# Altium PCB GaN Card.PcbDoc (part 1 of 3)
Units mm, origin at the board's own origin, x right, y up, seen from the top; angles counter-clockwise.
Board outline 50 x 40 mm, 6 copper layers (Top Layer, MidLayer1, MidLayer2, MidLayer3, MidLayer4, Bottom Layer), stack 1.981 mm thick; 88 components, 77 nets, 322 pads, 257 vias.
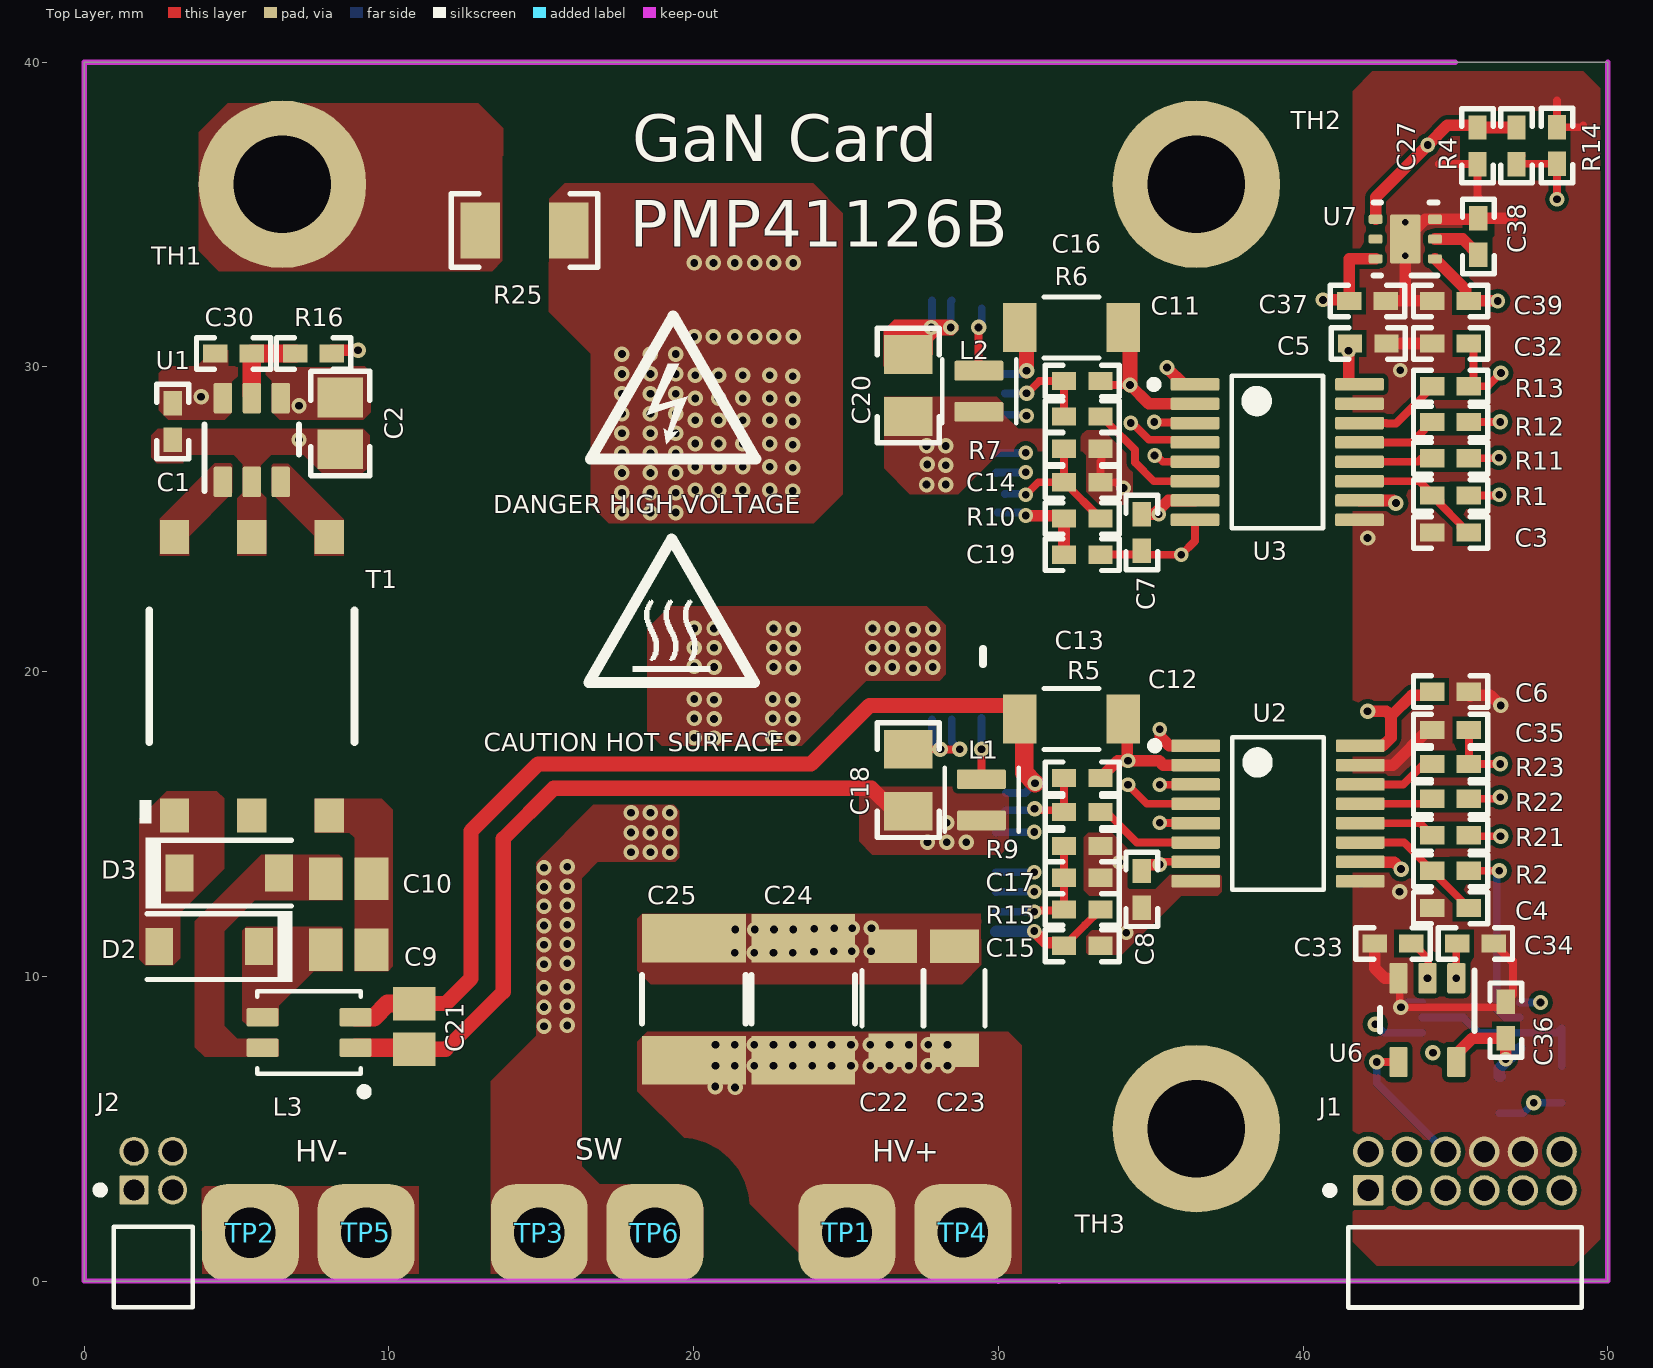
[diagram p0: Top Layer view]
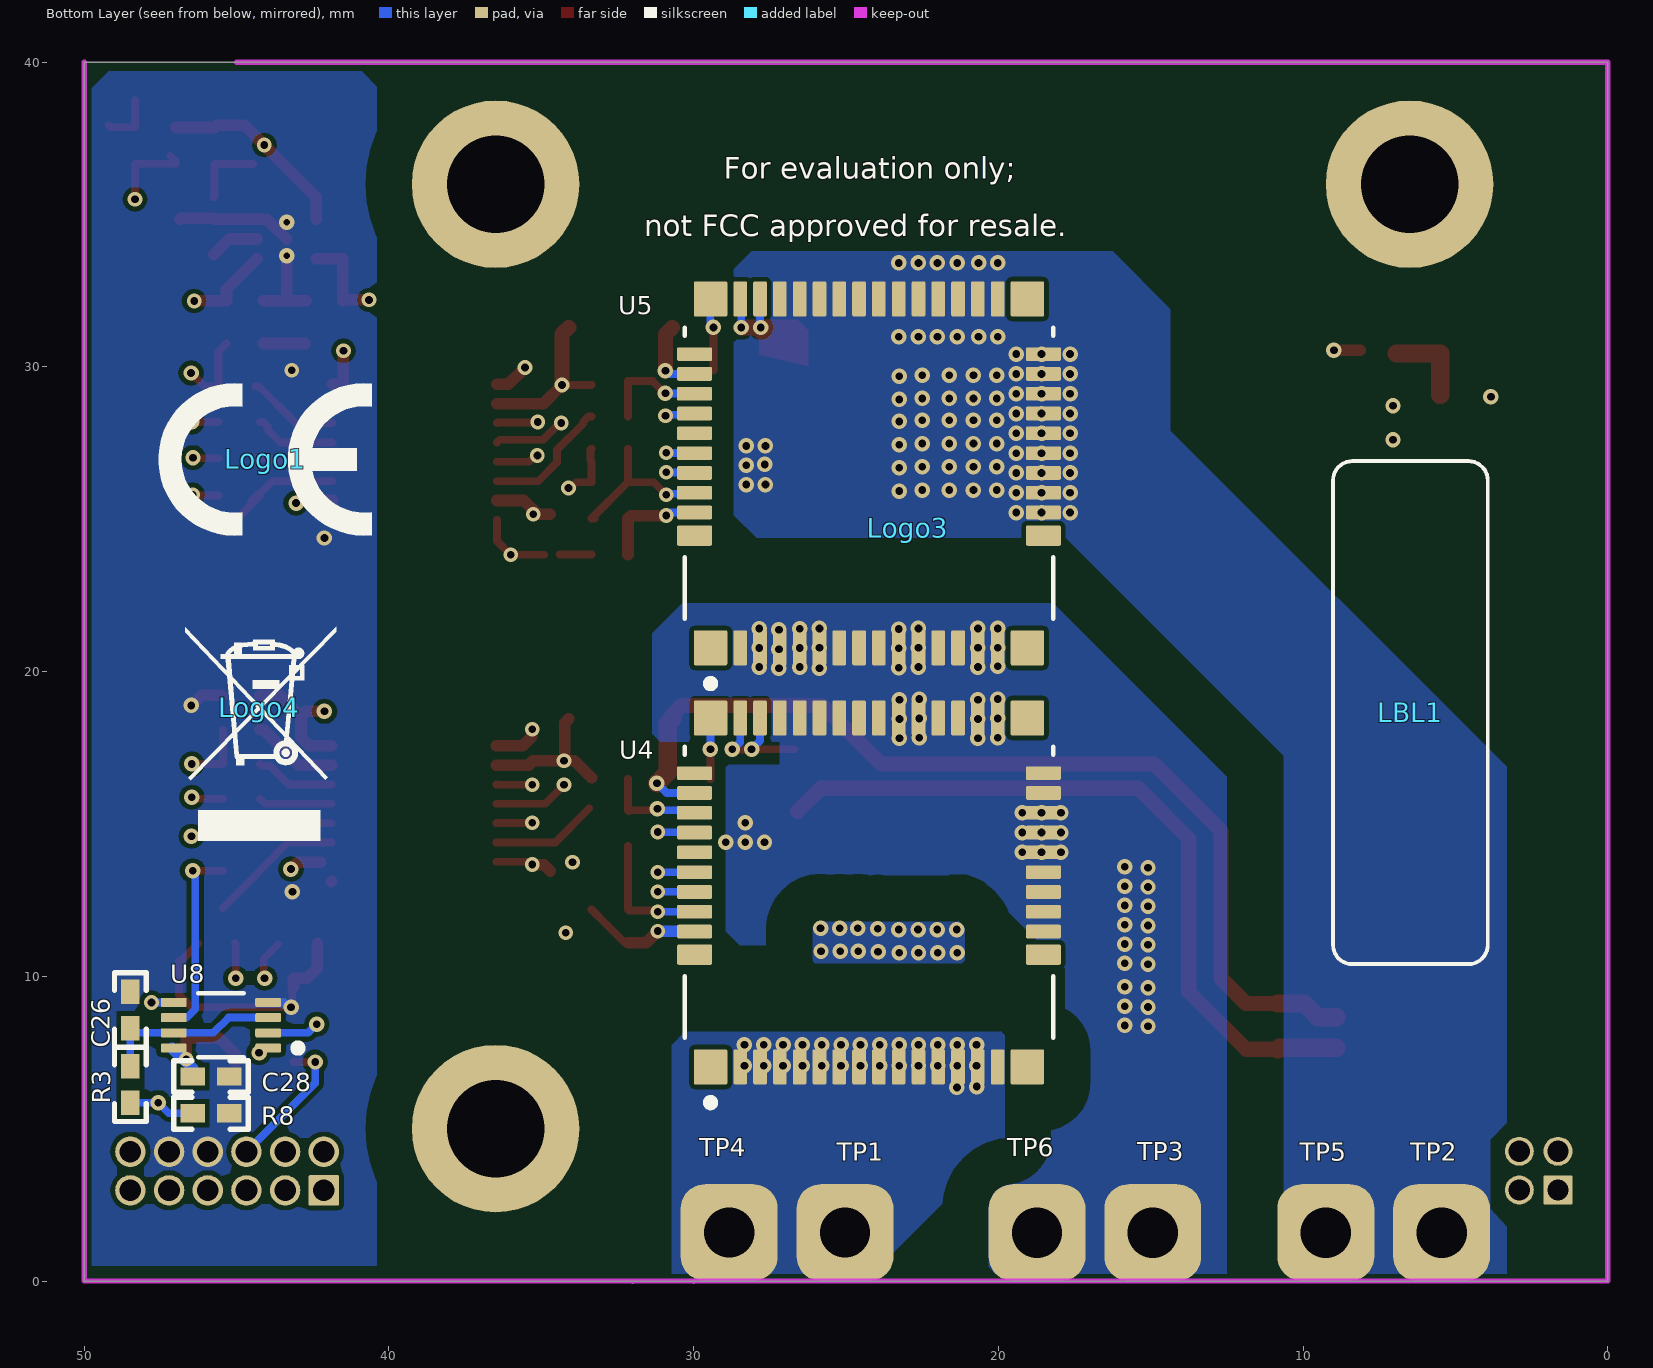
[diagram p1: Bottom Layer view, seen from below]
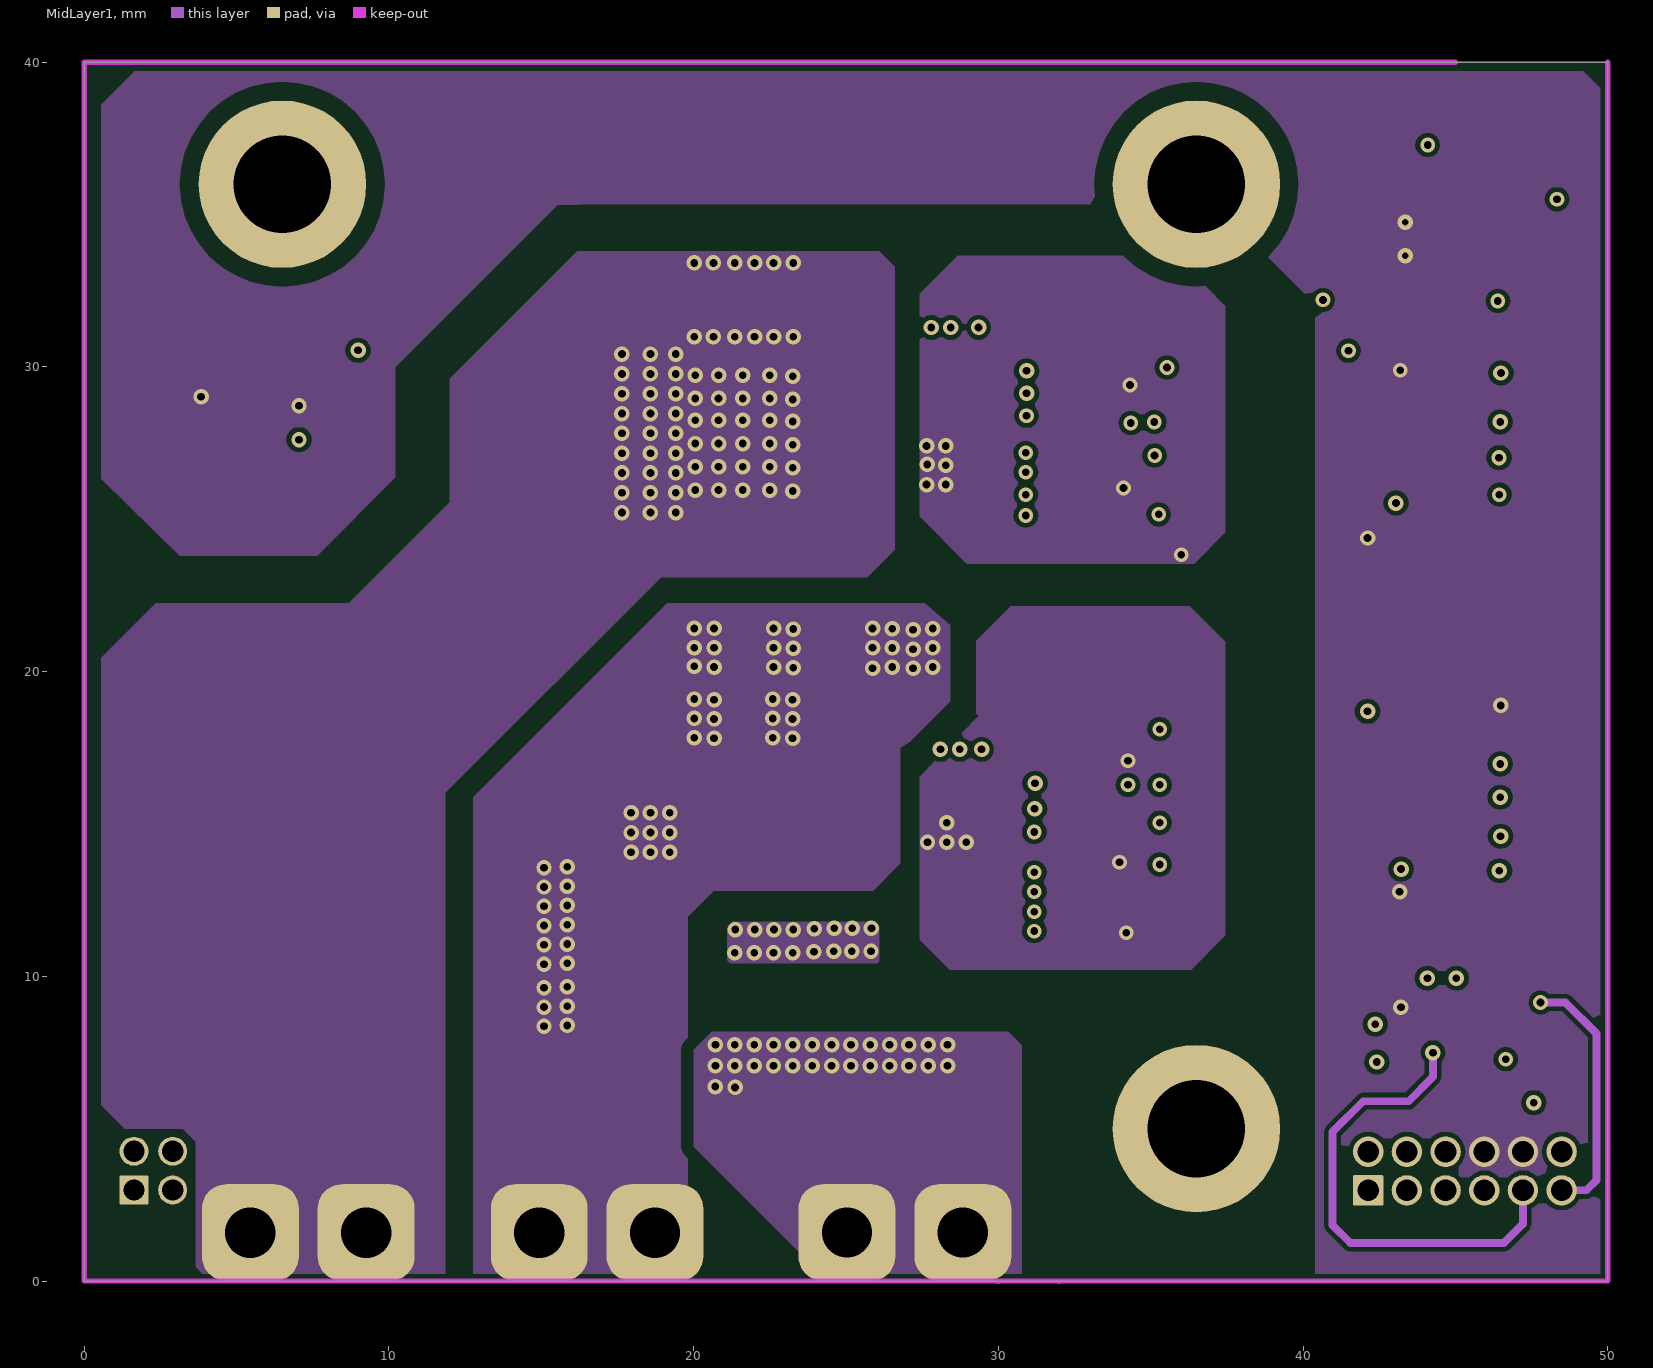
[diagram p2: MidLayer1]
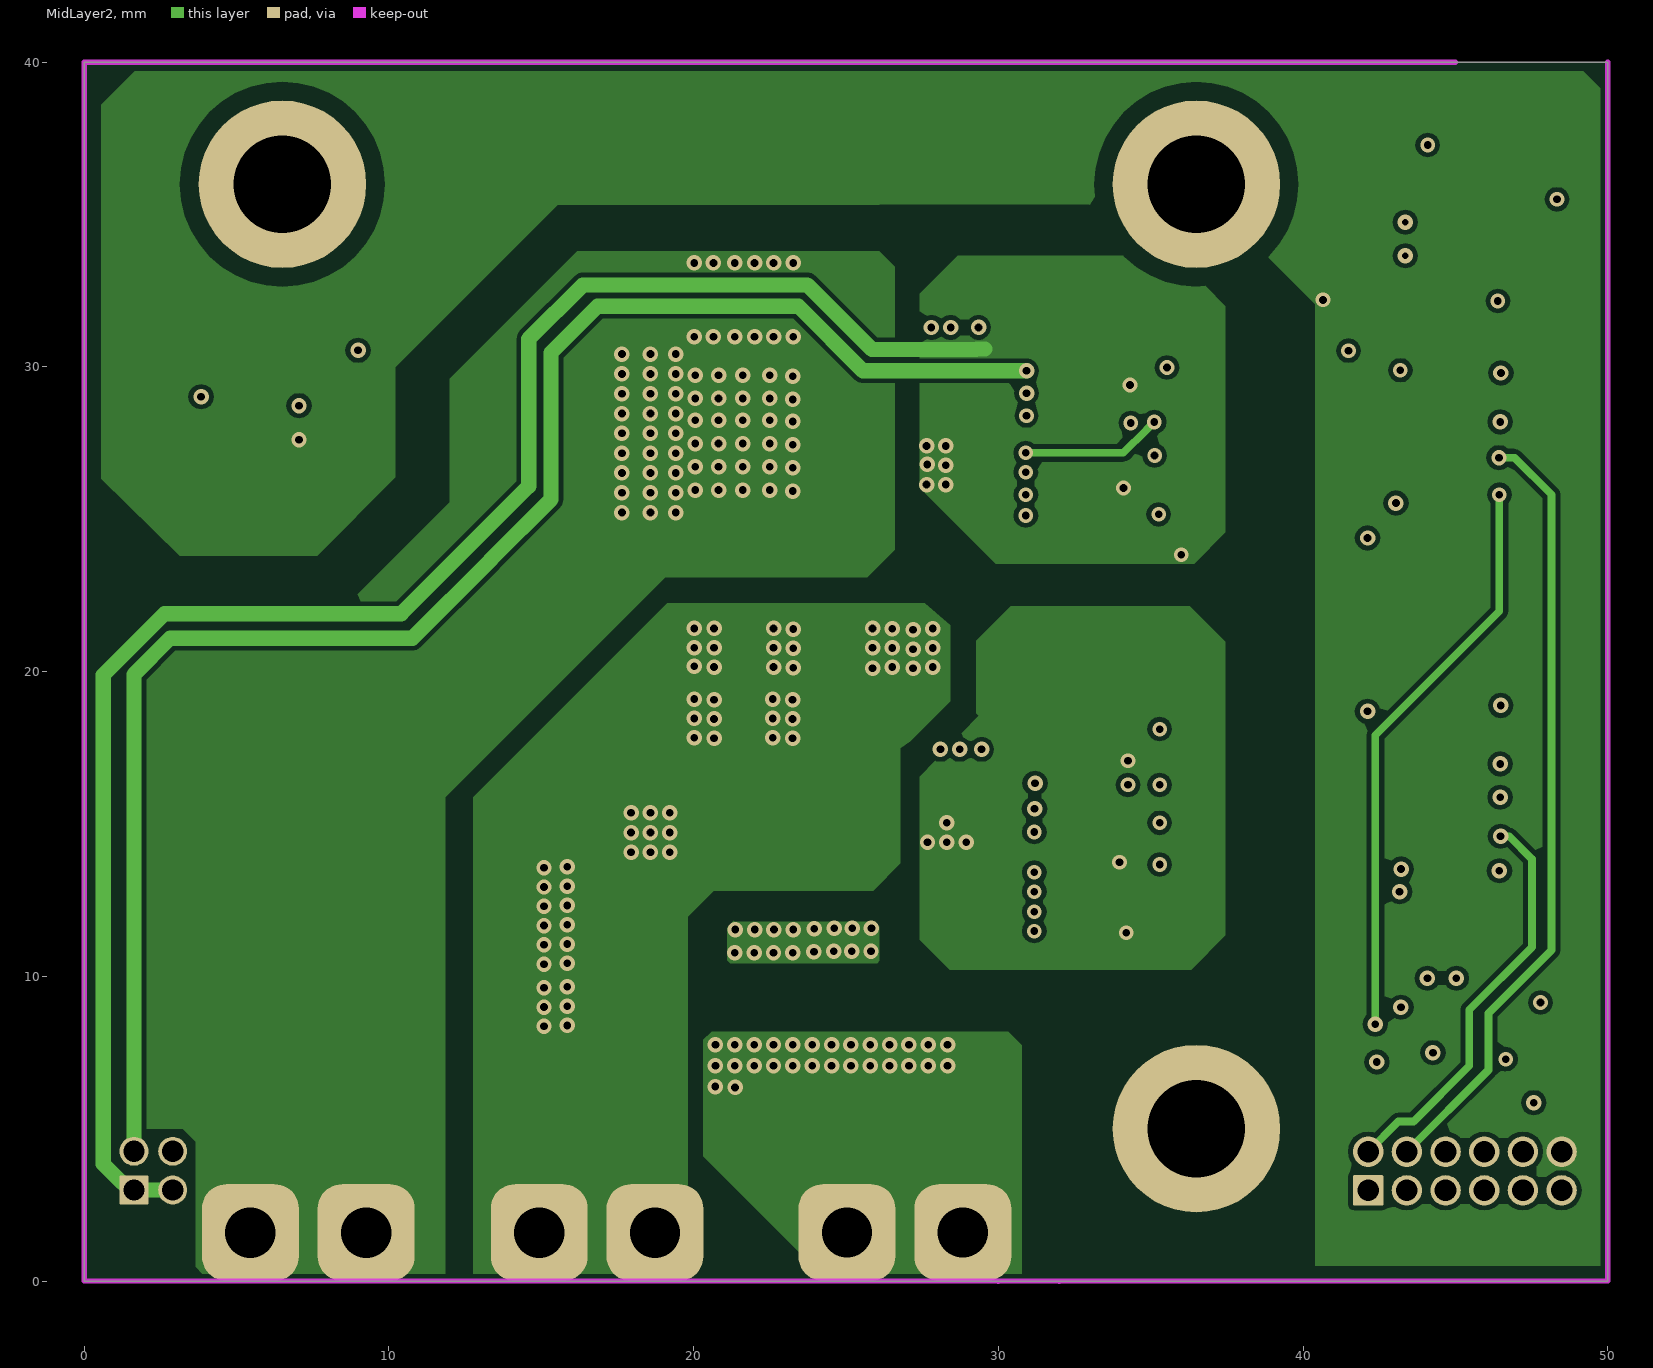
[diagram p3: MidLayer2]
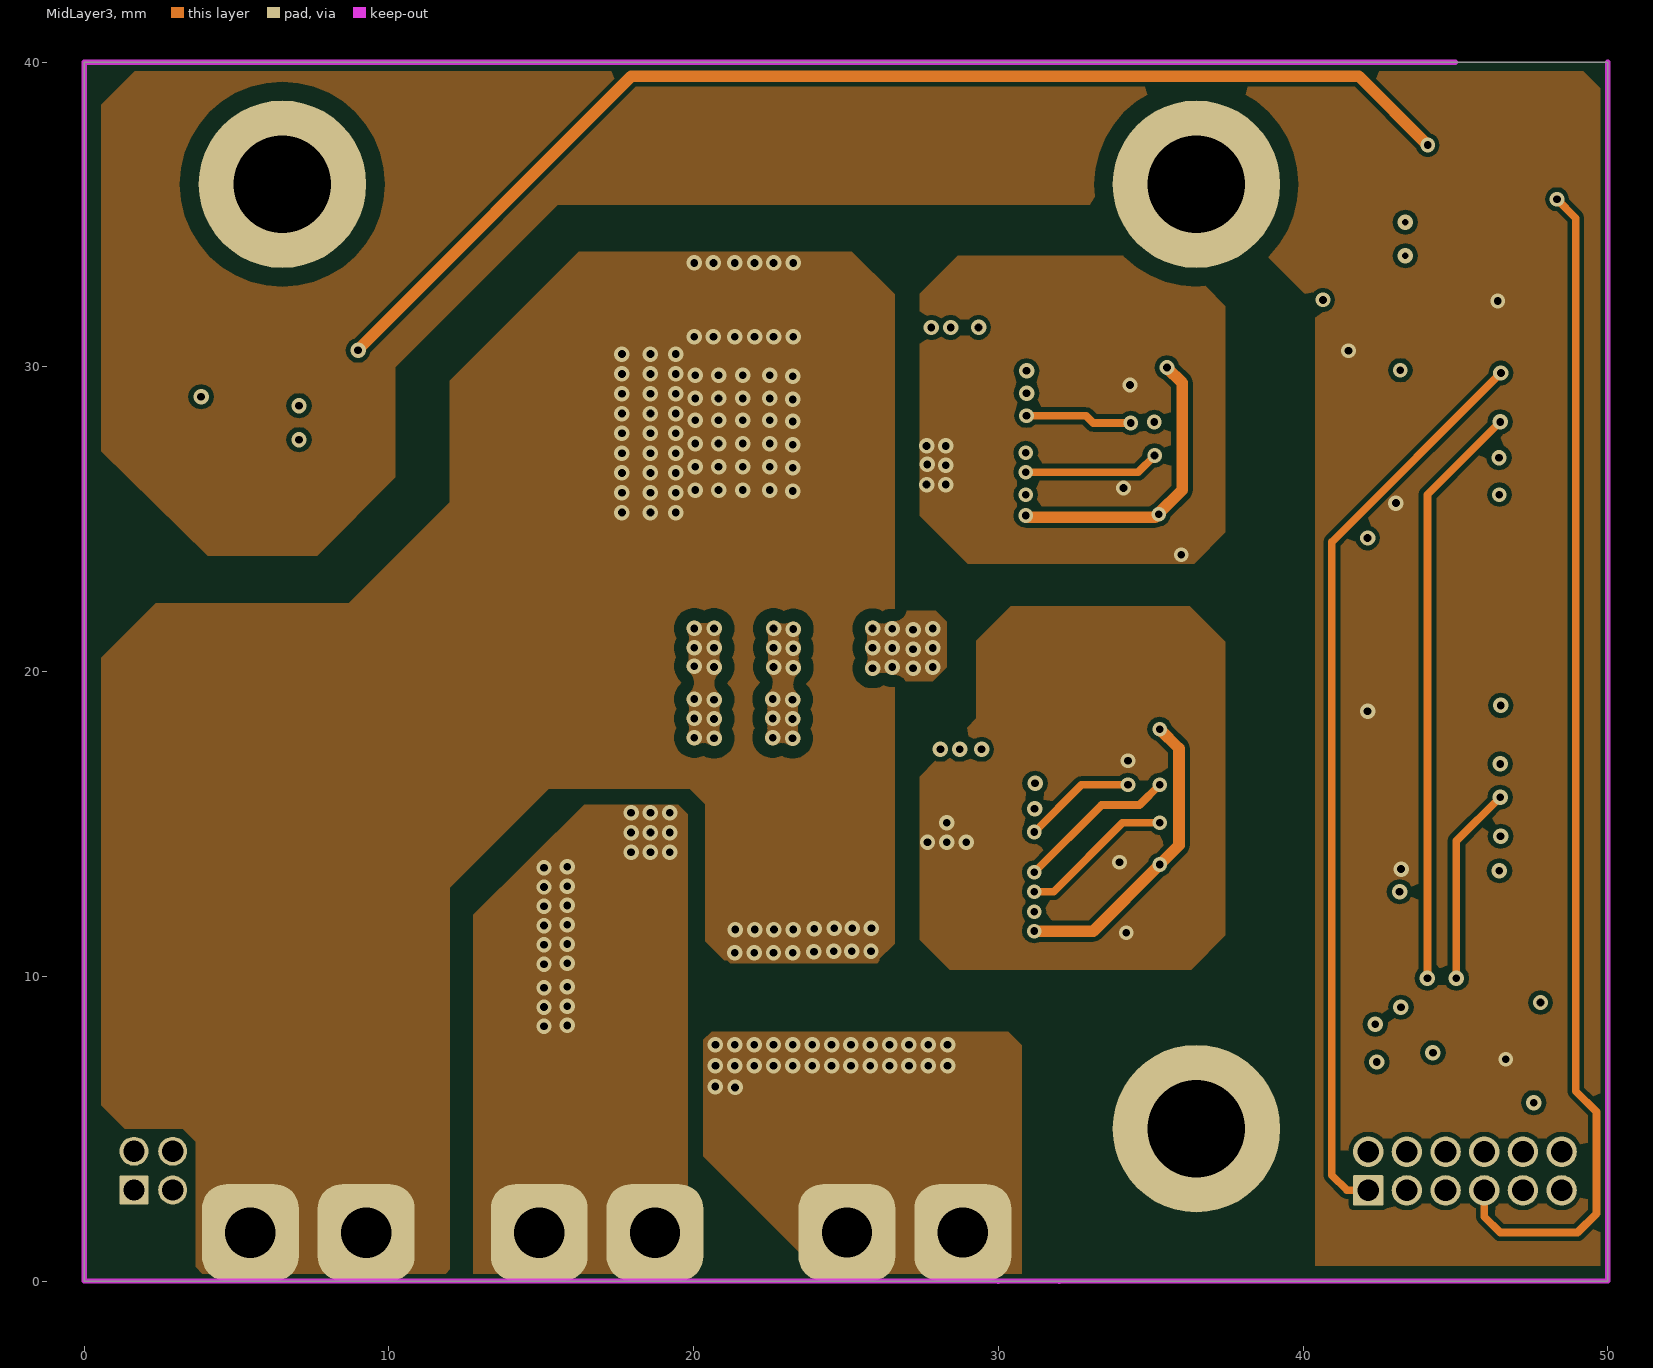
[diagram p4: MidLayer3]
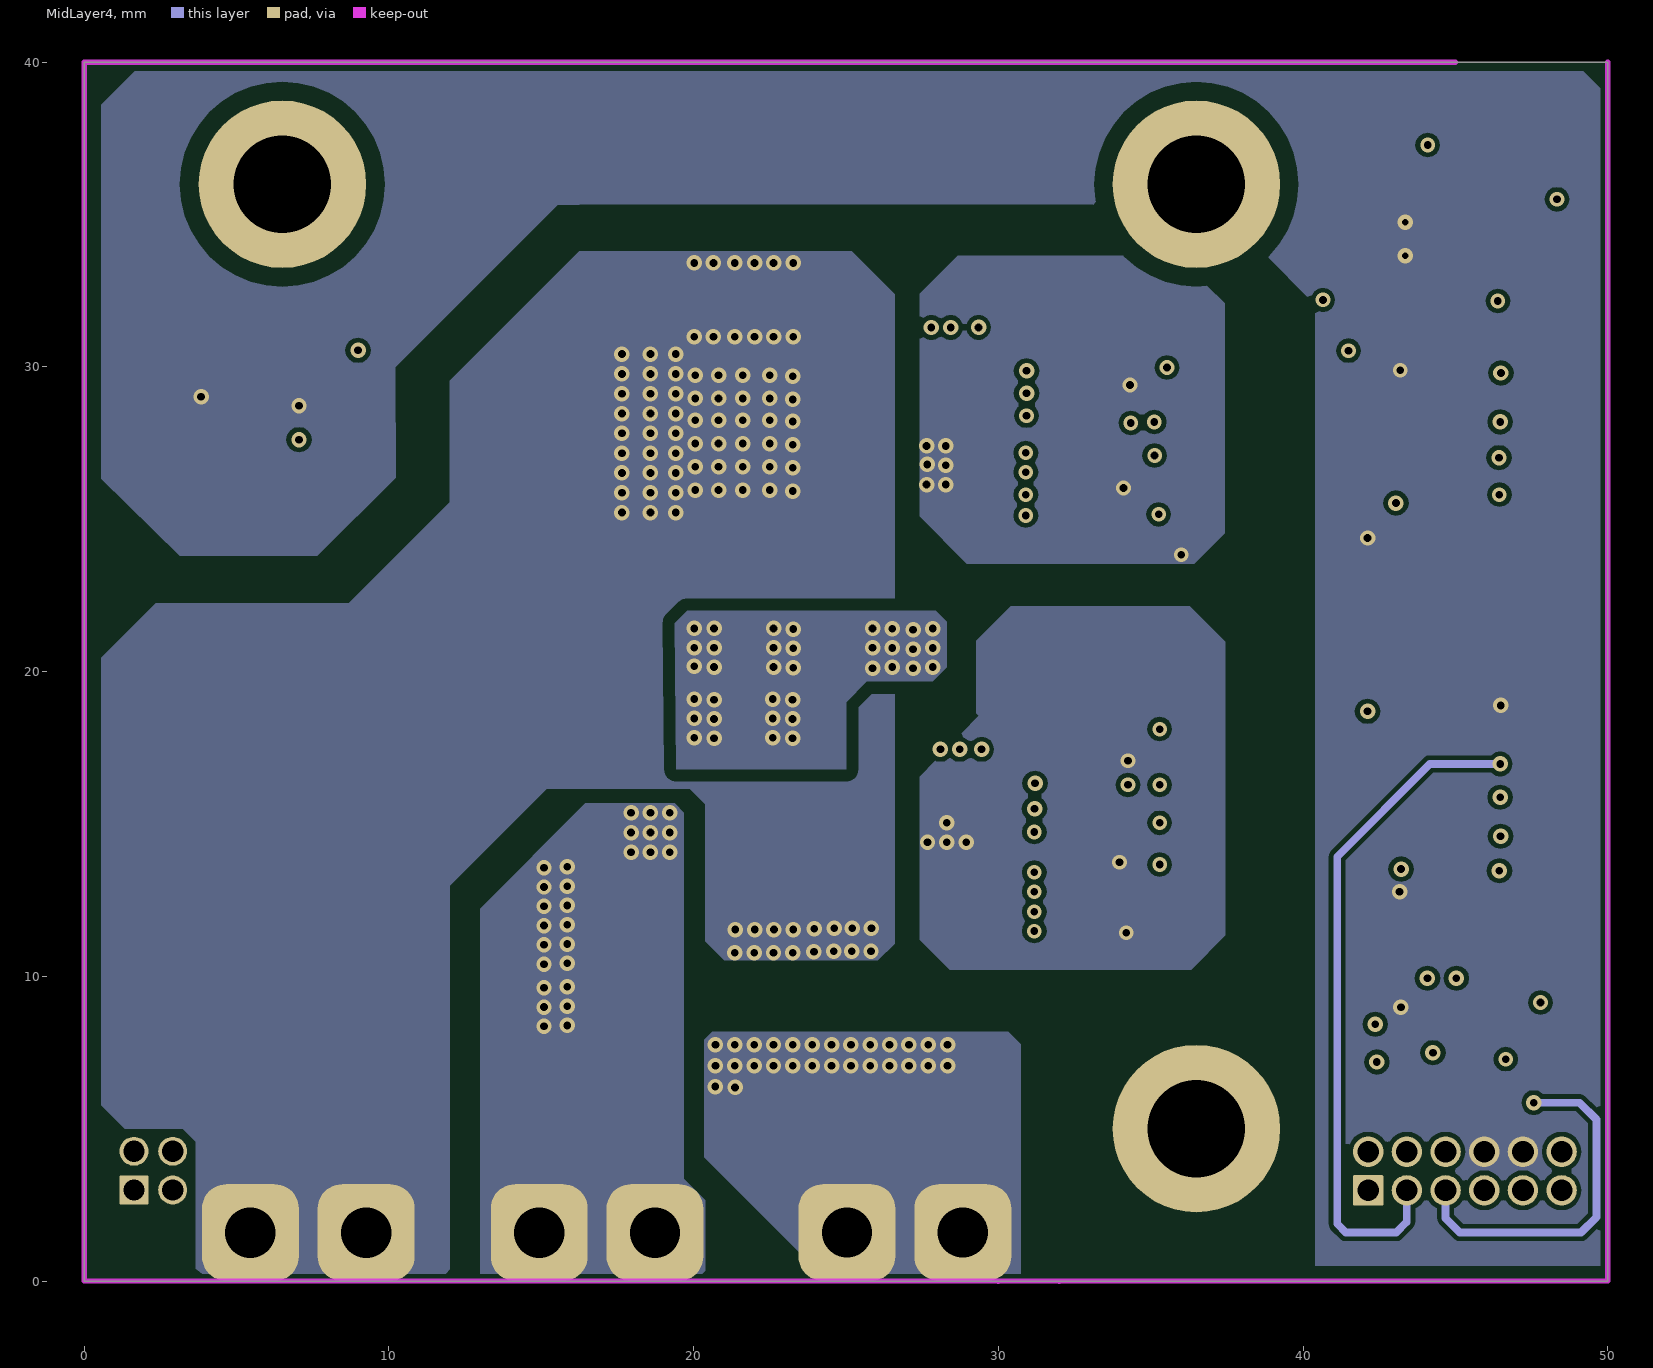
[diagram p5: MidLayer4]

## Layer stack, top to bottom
Top Solder: solder mask 0.0102, Solder Resist, Dk 3.5
Top Layer: signal copper 0.0711
Dielectric 1: prepreg 0.1168, FR-4 High Tg, Dk 4.2
MidLayer1: signal copper 0.0711
Dielectric 2: core 0.602, FR-4 High Tg, Dk 4.2
MidLayer2: signal copper 0.0711
4.6: prepreg 0.1168, FR-4 High Tg, Dk 4.2
MidLayer3: signal copper 0.0711
Dielectric 4: core 0.602, Dk 4.2
MidLayer4: signal copper 0.0711
Dielectric 5: prepreg 0.1168, Dk 4.2
Bottom Layer: signal copper 0.0711
Bottom Solder: solder mask 0.0102, Solder Resist, Dk 3.5

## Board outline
0,0 0,40 50,40 50,0 10,0

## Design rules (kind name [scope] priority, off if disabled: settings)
AcuteAngle [All] p1: minimum=4.50000000000000E+0001 checktracksonly=FALSE
AssemblyTestPointUsage [All] p1: valid=2
BoardOutlineClearance "Paste Layer 2" [OnLayer('Bottom Solder')] p1: gap=0 ignorepadtopadclearanceinfootprint=FALSE
BoardOutlineClearance "Paste Layer 1" [OnLayer('Top Solder')] p2: gap=0 ignorepadtopadclearanceinfootprint=FALSE
BoardOutlineClearance [OnCopper] p3: gap=0 ignorepadtopadclearanceinfootprint=FALSE
Clearance Clearance_VSW_Mid1 [(OnMultiLayer Or OnMid) And InNetClass('VSWNET') vs OnMid And Not InNetClass('VSWNET')] p1: gap=0.406 ignorepadtopadclearanceinfootprint=TRUE
Clearance Clearance_Screw_Top [InNetClass('Screw') vs OnLayer('Top Layer') And Not InNetClass('Screw')] p2: gap=1.524 ignorepadtopadclearanceinfootprint=TRUE
Clearance Clearance_Screw_Bottom [InNetClass('Screw') vs OnLayer('Bottom Layer') And Not InNetClass('Screw')] p3: gap=1.524 ignorepadtopadclearanceinfootprint=TRUE
Clearance Clearance_Screw_Other [InNetClass('Screw') vs Not OnLayer('Top Layer') AND Not OnLayer('Bottom Layer') AND Not InNetClass('Screw')] p4: gap=0.6 ignorepadtopadclearanceinfootprint=TRUE
Clearance Clearance_VSW_Mid2 [(OnMultiLayer Or OnMid) And Not InNetClass('VSWNET') vs OnMid And InNetClass('VSWNET')] p5: gap=0.406 ignorepadtopadclearanceinfootprint=TRUE
Clearance Clearance_VSW [InNetClass('VSWNET')   and OnCopper vs Not InNetClass('VSWNET') and OnCopper] p6: gap=1.524 ignorepadtopadclearanceinfootprint=TRUE
Clearance Clearance_VHV_Mid1 [(OnMultiLayer Or OnMid) And InNetClass('VHV') vs OnMid And Not InNetClass('VHV')] p7: gap=0.406 ignorepadtopadclearanceinfootprint=TRUE
Clearance Clearance_VHV_Mid2 [(OnMultiLayer Or OnMid) And Not InNetClass('VHV') vs OnMid And InNetClass('VHV')] p8: gap=0.406 ignorepadtopadclearanceinfootprint=TRUE
Clearance Clearance_VHV [InNetClass('VHV') vs Not InNetClass('VHV') and OnCopper] p9: gap=1.524 ignorepadtopadclearanceinfootprint=FALSE
Clearance Clearance_INGND [InNetClass('INGND') and OnCopper vs Not InNetClass('INGND')  and OnCopper] p10: gap=1.524 ignorepadtopadclearanceinfootprint=FALSE
Clearance [All] p11: gap=0.152 ignorepadtopadclearanceinfootprint=FALSE
ComponentClearance ComponentClearance_Shunt [InComponentClass('Header') vs InComponentClass('Shunt')] p1: gap=0 collisioncheckmode=3 verticalgap=0 showdistances=FALSE
ComponentClearance ComponentClearance_MountingHoles_FiducialMarks [InComponentClass('Mounting Holes') vs InComponentClass('FiducialMark')] p2 off: gap=1.27 collisioncheckmode=3 verticalgap=0.254 showdistances=FALSE
ComponentClearance ComponentClearance_Logo [InComponentClass('Logo')] p3: gap=0 collisioncheckmode=3 verticalgap=0.254 showdistances=FALSE
ComponentClearance ComponentClearance_ScrewToNut [(HasFootprint('NY PMS 440 0025 PH')) vs (HasFootprint('Keystone_1902C'))] p4: gap=0.127 collisioncheckmode=3 verticalgap=0.254 showdistances=FALSE
ComponentClearance ComponentClearance_MountingHoles [InComponentClass('Mounting Holes')] p5: gap=6.35 collisioncheckmode=3 verticalgap=2540 showdistances=FALSE
ComponentClearance ComponentClearance_SmallPassives [HasFootprint('0201*') or HasFootprint('0402*') or HasFootprint('0508') or HasFootprint('0603*') or HasFootprint('0612') or HasFootprint('0805*') or HasFootprint('0815*') or HasFootprint('0830*') or HasFootprint('1206*') or HasFootprint('1210*') or HasFootprint('1808*') or HasFootprint('1812*') or HasFootprint('1825*') or HasFootprint('2010*') or HasFootprint('2220*') or HasFootprint('2225*') or HasFootprint('2512*') or HasFootprint('2728*') or HasFootprint('3518*') vs HasFootprint('0201*') or HasFootprint('0402*') or HasFootprint('0508') or HasFootprint('0603*') or HasFootprint('0612') or HasFootprint('0805*') or HasFootprint('0815*') or HasFootprint('0830*') or HasFootprint('1206*') or HasFootprint('1210*') or HasFootprint('1808*') or HasFootprint('1812*') or HasFootprint('1825*') or HasFootprint('2010*') or HasFootprint('2220*') or HasFootprint('2225*') or HasFootprint('2512*') or HasFootprint('2728*') or HasFootprint('3518*')] p6: gap=0.025 collisioncheckmode=3 verticalgap=0.254 showdistances=FALSE
ComponentClearance ComponentClearance_THtoSMT [IsThruComponent vs IsSMTComponent] p7: gap=0.254 collisioncheckmode=3 verticalgap=0.762 showdistances=FALSE
ComponentClearance ComponentClearance_THtoTH [IsThruComponent vs IsThruComponent] p8: gap=0.3 collisioncheckmode=3 verticalgap=0.762 showdistances=FALSE
ComponentClearance [All] p9: gap=0.025 collisioncheckmode=3 verticalgap=0.254 showdistances=FALSE
DiffPairsRouting [All] p1: maxlimit=2.54 minlimit=0.254 mostfreqgap=0.254 substack1={A02F224D-4808-492E-A71F-5F5656FBF0D4} toplayer_{a02f224d-4808-492e-a71f-5f5656fbf0d4}_minwidth=0.381 toplayer_{a02f224d-4808-492e-a71f-5f5656fbf0d4}_maxwidth=0.381 toplayer_{a02f224d-4808-492e-a71f-5f5656fbf0d4}_prefwidth=0.381 midlayer1_{a02f224d-4808-492e-a71f-5f5656fbf0d4}_minwidth=0.381 midlayer1_{a02f224d-4808-492e-a71f-5f5656fbf0d4}_maxwidth=0.381 midlayer1_{a02f224d-4808-492e-a71f-5f5656fbf0d4}_prefwidth=0.381 midlayer2_{a02f224d-4808-492e-a71f-5f5656fbf0d4}_minwidth=0.381 midlayer2_{a02f224d-4808-492e-a71f-5f5656fbf0d4}_maxwidth=0.381 midlayer2_{a02f224d-4808-492e-a71f-5f5656fbf0d4}_prefwidth=0.381 midlayer3_{a02f224d-4808-492e-a71f-5f5656fbf0d4}_minwidth=0.381 midlayer3_{a02f224d-4808-492e-a71f-5f5656fbf0d4}_maxwidth=0.381 midlayer3_{a02f224d-4808-492e-a71f-5f5656fbf0d4}_prefwidth=0.381 midlayer4_{a02f224d-4808-492e-a71f-5f5656fbf0d4}_minwidth=0.381 midlayer4_{a02f224d-4808-492e-a71f-5f5656fbf0d4}_maxwidth=0.381 midlayer4_{a02f224d-4808-492e-a71f-5f5656fbf0d4}_prefwidth=0.381 bottomlayer_{a02f224d-4808-492e-a71f-5f5656fbf0d4}_minwidth=0.381 bottomlayer_{a02f224d-4808-492e-a71f-5f5656fbf0d4}_maxwidth=0.381 bottomlayer_{a02f224d-4808-492e-a71f-5f5656fbf0d4}_prefwidth=0.381 substack2={B838D286-A00B-4EE2-88E1-F79279CC64B4} toplayer_{b838d286-a00b-4ee2-88e1-f79279cc64b4}_minwidth=0.381 toplayer_{b838d286-a00b-4ee2-88e1-f79279cc64b4}_maxwidth=0.381 toplayer_{b838d286-a00b-4ee2-88e1-f79279cc64b4}_prefwidth=0.381 midlayer1_{b838d286-a00b-4ee2-88e1-f79279cc64b4}_minwidth=0.381 midlayer1_{b838d286-a00b-4ee2-88e1-f79279cc64b4}_maxwidth=0.381 midlayer1_{b838d286-a00b-4ee2-88e1-f79279cc64b4}_prefwidth=0.381 midlayer2_{b838d286-a00b-4ee2-88e1-f79279cc64b4}_minwidth=0.381 midlayer2_{b838d286-a00b-4ee2-88e1-f79279cc64b4}_maxwidth=0.381 midlayer2_{b838d286-a00b-4ee2-88e1-f79279cc64b4}_prefwidth=0.381 midlayer3_{b838d286-a00b-4ee2-88e1-f79279cc64b4}_minwidth=0.381 midlayer3_{b838d286-a00b-4ee2-88e1-f79279cc64b4}_maxwidth=0.381 midlayer3_{b838d286-a00b-4ee2-88e1-f79279cc64b4}_prefwidth=0.381 midlayer4_{b838d286-a00b-4ee2-88e1-f79279cc64b4}_minwidth=0.381 midlayer4_{b838d286-a00b-4ee2-88e1-f79279cc64b4}_maxwidth=0.381 midlayer4_{b838d286-a00b-4ee2-88e1-f79279cc64b4}_prefwidth=0.381 bottomlayer_{b838d286-a00b-4ee2-88e1-f79279cc64b4}_minwidth=0.381 bottomlayer_{b838d286-a00b-4ee2-88e1-f79279cc64b4}_maxwidth=0.381 bottomlayer_{b838d286-a00b-4ee2-88e1-f79279cc64b4}_prefwidth=0.381 substack3={88BCB183-C685-456E-B90A-365A53404C2C} toplayer_{88bcb183-c685-456e-b90a-365a53404c2c}_minwidth=0.381 toplayer_{88bcb183-c685-456e-b90a-365a53404c2c}_maxwidth=0.381 toplayer_{88bcb183-c685-456e-b90a-365a53404c2c}_prefwidth=0.381 midlayer1_{88bcb183-c685-456e-b90a-365a53404c2c}_minwidth=0.381 midlayer1_{88bcb183-c685-456e-b90a-365a53404c2c}_maxwidth=0.381 midlayer1_{88bcb183-c685-456e-b90a-365a53404c2c}_prefwidth=0.381 midlayer2_{88bcb183-c685-456e-b90a-365a53404c2c}_minwidth=0.381 midlayer2_{88bcb183-c685-456e-b90a-365a53404c2c}_maxwidth=0.381 midlayer2_{88bcb183-c685-456e-b90a-365a53404c2c}_prefwidth=0.381 midlayer3_{88bcb183-c685-456e-b90a-365a53404c2c}_minwidth=0.381 midlayer3_{88bcb183-c685-456e-b90a-365a53404c2c}_maxwidth=0.381 midlayer3_{88bcb183-c685-456e-b90a-365a53404c2c}_prefwidth=0.381 midlayer4_{88bcb183-c685-456e-b90a-365a53404c2c}_minwidth=0.381 midlayer4_{88bcb183-c685-456e-b90a-365a53404c2c}_maxwidth=0.381 midlayer4_{88bcb183-c685-456e-b90a-365a53404c2c}_prefwidth=0.381 bottomlayer_{88bcb183-c685-456e-b90a-365a53404c2c}_minwidth=0.381 bottomlayer_{88bcb183-c685-456e-b90a-365a53404c2c}_maxwidth=0.381 bottomlayer_{88bcb183-c685-456e-b90a-365a53404c2c}_prefwidth=0.381 substack4={4C8C2325-90D5-40B8-8B6B-4F66D44EFE25} toplayer_{4c8c2325-90d5-40b8-8b6b-4f66d44efe25}_minwidth=0.381 toplayer_{4c8c2325-90d5-40b8-8b6b-4f66d44efe25}_maxwidth=0.381 toplayer_{4c8c2325-90d5-40b8-8b6b-4f66d44efe25}_prefwidth=0.381 midlayer1_{4c8c2325-90d5-40b8-8b6b-4f66d44efe25}_minwidth=0.381 midlayer1_{4c8c2325-90d5-40b8-8b6b-4f66d44efe25}_maxwidth=0.381 midlayer1_{4c8c2325-90d5-40b8-8b6b-4f66d44efe25}_prefwidth=0.381 midlayer2_{4c8c2325-90d5-40b8-8b6b-4f66d44efe25}_minwidth=0.381 midlayer2_{4c8c2325-90d5-40b8-8b6b-4f66d44efe25}_maxwidth=0.381 midlayer2_{4c8c2325-90d5-40b8-8b6b-4f66d44efe25}_prefwidth=0.381 midlayer3_{4c8c2325-90d5-40b8-8b6b-4f66d44efe25}_minwidth=0.381 midlayer3_{4c8c2325-90d5-40b8-8b6b-4f66d44efe25}_maxwidth=0.381 midlayer3_{4c8c2325-90d5-40b8-8b6b-4f66d44efe25}_prefwidth=0.381 midlayer4_{4c8c2325-90d5-40b8-8b6b-4f66d44efe25}_minwidth=0.381 midlayer4_{4c8c2325-90d5-40b8-8b6b-4f66d44efe25}_maxwidth=0.381 midlayer4_{4c8c2325-90d5-40b8-8b6b-4f66d44efe25}_prefwidth=0.381 bottomlayer_{4c8c2325-90d5-40b8-8b6b-4f66d44efe25}_minwidth=0.381 bottomlayer_{4c8c2325-90d5-40b8-8b6b-4f66d44efe25}_maxwidth=0.381 bottomlayer_{4c8c2325-90d5-40b8-8b6b-4f66d44efe25}_prefwidth=0.381 toplayer_minwidth=0.381 toplayer_maxwidth=0.381 toplayer_prefwidth=0.381 midlayer1_minwidth=0.381 midlayer1_maxwidth=0.381 midlayer1_prefwidth=0.381 midlayer2_minwidth=0.381 midlayer2_maxwidth=0.381 midlayer2_prefwidth=0.381 midlayer3_minwidth=0.381 midlayer3_maxwidth=0.381 midlayer3_prefwidth=0.381 midlayer4_minwidth=0.381 midlayer4_maxwidth=0.381 midlayer4_prefwidth=0.381 bottomlayer_minwidth=0.381 bottomlayer_maxwidth=0.381 bottomlayer_prefwidth=0.381 substack5={553D66F5-99EF-40B1-BA7C-73E3B04B176F} toplayer_{553d66f5-99ef-40b1-ba7c-73e3b04b176f}_minwidth=0.381 toplayer_{553d66f5-99ef-40b1-ba7c-73e3b04b176f}_maxwidth=0.381 toplayer_{553d66f5-99ef-40b1-ba7c-73e3b04b176f}_prefwidth=0.381 midlayer1_{553d66f5-99ef-40b1-ba7c-73e3b04b176f}_minwidth=0.381 midlayer1_{553d66f5-99ef-40b1-ba7c-73e3b04b176f}_maxwidth=0.381 midlayer1_{553d66f5-99ef-40b1-ba7c-73e3b04b176f}_prefwidth=0.381 midlayer2_{553d66f5-99ef-40b1-ba7c-73e3b04b176f}_minwidth=0.381 midlayer2_{553d66f5-99ef-40b1-ba7c-73e3b04b176f}_maxwidth=0.381 midlayer2_{553d66f5-99ef-40b1-ba7c-73e3b04b176f}_prefwidth=0.381 midlayer3_{553d66f5-99ef-40b1-ba7c-73e3b04b176f}_minwidth=0.381 midlayer3_{553d66f5-99ef-40b1-ba7c-73e3b04b176f}_maxwidth=0.381 midlayer3_{553d66f5-99ef-40b1-ba7c-73e3b04b176f}_prefwidth=0.381 midlayer4_{553d66f5-99ef-40b1-ba7c-73e3b04b176f}_minwidth=0.381 midlayer4_{553d66f5-99ef-40b1-ba7c-73e3b04b176f}_maxwidth=0.381 midlayer4_{553d66f5-99ef-40b1-ba7c-73e3b04b176f}_prefwidth=0.381 bottomlayer_{553d66f5-99ef-40b1-ba7c-73e3b04b176f}_minwidth=0.381 bottomlayer_{553d66f5-99ef-40b1-ba7c-73e3b04b176f}_maxwidth=0.381 bottomlayer_{553d66f5-99ef-40b1-ba7c-73e3b04b176f}_prefwidth=0.381 substack6={FF0C9878-5A48-402E-B013-8E2EEFCEDCCB} toplayer_{ff0c9878-5a48-402e-b013-8e2eefcedccb}_minwidth=0.381 toplayer_{ff0c9878-5a48-402e-b013-8e2eefcedccb}_maxwidth=0.381 toplayer_{ff0c9878-5a48-402e-b013-8e2eefcedccb}_prefwidth=0.381 midlayer1_{ff0c9878-5a48-402e-b013-8e2eefcedccb}_minwidth=0.381 midlayer1_{ff0c9878-5a48-402e-b013-8e2eefcedccb}_maxwidth=0.381 midlayer1_{ff0c9878-5a48-402e-b013-8e2eefcedccb}_prefwidth=0.381 midlayer2_{ff0c9878-5a48-402e-b013-8e2eefcedccb}_minwidth=0.381 midlayer2_{ff0c9878-5a48-402e-b013-8e2eefcedccb}_maxwidth=0.381 midlayer2_{ff0c9878-5a48-402e-b013-8e2eefcedccb}_prefwidth=0.381 midlayer3_{ff0c9878-5a48-402e-b013-8e2eefcedccb}_minwidth=0.381 midlayer3_{ff0c9878-5a48-402e-b013-8e2eefcedccb}_maxwidth=0.381 midlayer3_{ff0c9878-5a48-402e-b013-8e2eefcedccb}_prefwidth=0.381 midlayer4_{ff0c9878-5a48-402e-b013-8e2eefcedccb}_minwidth=0.381 midlayer4_{ff0c9878-5a48-402e-b013-8e2eefcedccb}_maxwidth=0.381 midlayer4_{ff0c9878-5a48-402e-b013-8e2eefcedccb}_prefwidth=0.381 bottomlayer_{ff0c9878-5a48-402e-b013-8e2eefcedccb}_minwidth=0.381 bottomlayer_{ff0c9878-5a48-402e-b013-8e2eefcedccb}_maxwidth=0.381 bottomlayer_{ff0c9878-5a48-402e-b013-8e2eefcedccb}_prefwidth=0.381 substack7={5BB5B65B-6C7F-4868-A6AE-66DD57ADDCBD} toplayer_{5bb5b65b-6c7f-4868-a6ae-66dd57addcbd}_minwidth=0.381 toplayer_{5bb5b65b-6c7f-4868-a6ae-66dd57addcbd}_maxwidth=0.381 toplayer_{5bb5b65b-6c7f-4868-a6ae-66dd57addcbd}_prefwidth=0.381 midlayer1_{5bb5b65b-6c7f-4868-a6ae-66dd57addcbd}_minwidth=0.381 midlayer1_{5bb5b65b-6c7f-4868-a6ae-66dd57addcbd}_maxwidth=0.381 midlayer1_{5bb5b65b-6c7f-4868-a6ae-66dd57addcbd}_prefwidth=0.381 midlayer2_{5bb5b65b-6c7f-4868-a6ae-66dd57addcbd}_minwidth=0.381 midlayer2_{5bb5b65b-6c7f-4868-a6ae-66dd57addcbd}_maxwidth=0.381 midlayer2_{5bb5b65b-6c7f-4868-a6ae-66dd57addcbd}_prefwidth=0.381 midlayer3_{5bb5b65b-6c7f-4868-a6ae-66dd57addcbd}_minwidth=0.381 midlayer3_{5bb5b65b-6c7f-4868-a6ae-66dd57addcbd}_maxwidth=0.381 midlayer3_{5bb5b65b-6c7f-4868-a6ae-66dd57addcbd}_prefwidth=0.381 midlayer4_{5bb5b65b-6c7f-4868-a6ae-66dd57addcbd}_minwidth=0.381 midlayer4_{5bb5b65b-6c7f-4868-a6ae-66dd57addcbd}_maxwidth=0.381 midlayer4_{5bb5b65b-6c7f-4868-a6ae-66dd57addcbd}_prefwidth=0.381 bottomlayer_{5bb5b65b-6c7f-4868-a6ae-66dd57addcbd}_minwidth=0.381 bottomlayer_{5bb5b65b-6c7f-4868-a6ae-66dd57addcbd}_maxwidth=0.381 bottomlayer_{5bb5b65b-6c7f-4868-a6ae-66dd57addcbd}_prefwidth=0.381 substack8={590F0BEA-1E04-4904-B9C9-D9D160075BC2} toplayer_{590f0bea-1e04-4904-b9c9-d9d160075bc2}_minwidth=0.381 toplayer_{590f0bea-1e04-4904-b9c9-d9d160075bc2}_maxwidth=0.381 toplayer_{590f0bea-1e04-4904-b9c9-d9d160075bc2}_prefwidth=0.381 midlayer1_{590f0bea-1e04-4904-b9c9-d9d160075bc2}_minwidth=0.381 midlayer1_{590f0bea-1e04-4904-b9c9-d9d160075bc2}_maxwidth=0.381 midlayer1_{590f0bea-1e04-4904-b9c9-d9d160075bc2}_prefwidth=0.381 midlayer2_{590f0bea-1e04-4904-b9c9-d9d160075bc2}_minwidth=0.381 midlayer2_{590f0bea-1e04-4904-b9c9-d9d160075bc2}_maxwidth=0.381 midlayer2_{590f0bea-1e04-4904-b9c9-d9d160075bc2}_prefwidth=0.381 midlayer3_{590f0bea-1e04-4904-b9c9-d9d160075bc2}_minwidth=0.381 midlayer3_{590f0bea-1e04-4904-b9c9-d9d160075bc2}_maxwidth=0.381 midlayer3_{590f0bea-1e04-4904-b9c9-d9d160075bc2}_prefwidth=0.381 midlayer4_{590f0bea-1e04-4904-b9c9-d9d160075bc2}_minwidth=0.381 midlayer4_{590f0bea-1e04-4904-b9c9-d9d160075bc2}_maxwidth=0.381 midlayer4_{590f0bea-1e04-4904-b9c9-d9d160075bc2}_prefwidth=0.381 bottomlayer_{590f0bea-1e04-4904-b9c9-d9d160075bc2}_minwidth=0.381 bottomlayer_{590f0bea-1e04-4904-b9c9-d9d160075bc2}_maxwidth=0.381 bottomlayer_{590f0bea-1e04-4904-b9c9-d9d160075bc2}_prefwidth=0.381 substack9={B2AC4F48-1A5F-44D7-A91B-3BAADFDAAED0} toplayer_{b2ac4f48-1a5f-44d7-a91b-3baadfdaaed0}_minwidth=0.381 toplayer_{b2ac4f48-1a5f-44d7-a91b-3baadfdaaed0}_maxwidth=0.381 toplayer_{b2ac4f48-1a5f-44d7-a91b-3baadfdaaed0}_prefwidth=0.381 midlayer1_{b2ac4f48-1a5f-44d7-a91b-3baadfdaaed0}_minwidth=0.381 midlayer1_{b2ac4f48-1a5f-44d7-a91b-3baadfdaaed0}_maxwidth=0.381 midlayer1_{b2ac4f48-1a5f-44d7-a91b-3baadfdaaed0}_prefwidth=0.381 midlayer2_{b2ac4f48-1a5f-44d7-a91b-3baadfdaaed0}_minwidth=0.381 midlayer2_{b2ac4f48-1a5f-44d7-a91b-3baadfdaaed0}_maxwidth=0.381 midlayer2_{b2ac4f48-1a5f-44d7-a91b-3baadfdaaed0}_prefwidth=0.381 midlayer3_{b2ac4f48-1a5f-44d7-a91b-3baadfdaaed0}_minwidth=0.381 midlayer3_{b2ac4f48-1a5f-44d7-a91b-3baadfdaaed0}_maxwidth=0.381 midlayer3_{b2ac4f48-1a5f-44d7-a91b-3baadfdaaed0}_prefwidth=0.381 midlayer4_{b2ac4f48-1a5f-44d7-a91b-3baadfdaaed0}_minwidth=0.381 midlayer4_{b2ac4f48-1a5f-44d7-a91b-3baadfdaaed0}_maxwidth=0.381 midlayer4_{b2ac4f48-1a5f-44d7-a91b-3baadfdaaed0}_prefwidth=0.381 bottomlayer_{b2ac4f48-1a5f-44d7-a91b-3baadfdaaed0}_minwidth=0.381 bottomlayer_{b2ac4f48-1a5f-44d7-a91b-3baadfdaaed0}_maxwidth=0.381 bottomlayer_{b2ac4f48-1a5f-44d7-a91b-3baadfdaaed0}_prefwidth=0.381 substack10={DD3D4156-A54D-4E1F-B7FF-E5EF72C45496} toplayer_{dd3d4156-a54d-4e1f-b7ff-e5ef72c45496}_minwidth=0.381 toplayer_{dd3d4156-a54d-4e1f-b7ff-e5ef72c45496}_maxwidth=0.381 toplayer_{dd3d4156-a54d-4e1f-b7ff-e5ef72c45496}_prefwidth=0.381 midlayer1_{dd3d4156-a54d-4e1f-b7ff-e5ef72c45496}_minwidth=0.381 midlayer1_{dd3d4156-a54d-4e1f-b7ff-e5ef72c45496}_maxwidth=0.381 midlayer1_{dd3d4156-a54d-4e1f-b7ff-e5ef72c45496}_prefwidth=0.381 midlayer2_{dd3d4156-a54d-4e1f-b7ff-e5ef72c45496}_minwidth=0.381 midlayer2_{dd3d4156-a54d-4e1f-b7ff-e5ef72c45496}_maxwidth=0.381 midlayer2_{dd3d4156-a54d-4e1f-b7ff-e5ef72c45496}_prefwidth=0.381 midlayer3_{dd3d4156-a54d-4e1f-b7ff-e5ef72c45496}_minwidth=0.381 midlayer3_{dd3d4156-a54d-4e1f-b7ff-e5ef72c45496}_maxwidth=0.381 midlayer3_{dd3d4156-a54d-4e1f-b7ff-e5ef72c45496}_prefwidth=0.381 midlayer4_{dd3d4156-a54d-4e1f-b7ff-e5ef72c45496}_minwidth=0.381 midlayer4_{dd3d4156-a54d-4e1f-b7ff-e5ef72c45496}_maxwidth=0.381 midlayer4_{dd3d4156-a54d-4e1f-b7ff-e5ef72c45496}_prefwidth=0.381 bottomlayer_{dd3d4156-a54d-4e1f-b7ff-e5ef72c45496}_minwidth=0.381 bottomlayer_{dd3d4156-a54d-4e1f-b7ff-e5ef72c45496}_maxwidth=0.381 bottomlayer_{dd3d4156-a54d-4e1f-b7ff-e5ef72c45496}_prefwidth=0.381 substack11={7CC4AE65-1EB7-43C1-8FCA-3677EE54F737} toplayer_{7cc4ae65-1eb7-43c1-8fca-3677ee54f737}_minwidth=0.381 toplayer_{7cc4ae65-1eb7-43c1-8fca-3677ee54f737}_maxwidth=0.381 toplayer_{7cc4ae65-1eb7-43c1-8fca-3677ee54f737}_prefwidth=0.381 midlayer1_{7cc4ae65-1eb7-43c1-8fca-3677ee54f737}_minwidth=0.381 midlayer1_{7cc4ae65-1eb7-43c1-8fca-3677ee54f737}_maxwidth=0.381 midlayer1_{7cc4ae65-1eb7-43c1-8fca-3677ee54f737}_prefwidth=0.381 midlayer2_{7cc4ae65-1eb7-43c1-8fca-3677ee54f737}_minwidth=0.381 midlayer2_{7cc4ae65-1eb7-43c1-8fca-3677ee54f737}_maxwidth=0.381 midlayer2_{7cc4ae65-1eb7-43c1-8fca-3677ee54f737}_prefwidth=0.381 midlayer3_{7cc4ae65-1eb7-43c1-8fca-3677ee54f737}_minwidth=0.381 midlayer3_{7cc4ae65-1eb7-43c1-8fca-3677ee54f737}_maxwidth=0.381 midlayer3_{7cc4ae65-1eb7-43c1-8fca-3677ee54f737}_prefwidth=0.381 midlayer4_{7cc4ae65-1eb7-43c1-8fca-3677ee54f737}_minwidth=0.381 midlayer4_{7cc4ae65-1eb7-43c1-8fca-3677ee54f737}_maxwidth=0.381 midlayer4_{7cc4ae65-1eb7-43c1-8fca-3677ee54f737}_prefwidth=0.381 bottomlayer_{7cc4ae65-1eb7-43c1-8fca-3677ee54f737}_minwidth=0.381 bottomlayer_{7cc4ae65-1eb7-43c1-8fca-3677ee54f737}_maxwidth=0.381 bottomlayer_{7cc4ae65-1eb7-43c1-8fca-3677ee54f737}_prefwidth=0.381 substack12={E8C37195-128A-4AA0-B681-9B6788FCEC2F} toplayer_{e8c37195-128a-4aa0-b681-9b6788fcec2f}_minwidth=0.381 toplayer_{e8c37195-128a-4aa0-b681-9b6788fcec2f}_maxwidth=0.381 toplayer_{e8c37195-128a-4aa0-b681-9b6788fcec2f}_prefwidth=0.381 midlayer1_{e8c37195-128a-4aa0-b681-9b6788fcec2f}_minwidth=0.381 midlayer1_{e8c37195-128a-4aa0-b681-9b6788fcec2f}_maxwidth=0.381 midlayer1_{e8c37195-128a-4aa0-b681-9b6788fcec2f}_prefwidth=0.381 midlayer2_{e8c37195-128a-4aa0-b681-9b6788fcec2f}_minwidth=0.381 midlayer2_{e8c37195-128a-4aa0-b681-9b6788fcec2f}_maxwidth=0.381 midlayer2_{e8c37195-128a-4aa0-b681-9b6788fcec2f}_prefwidth=0.381 midlayer3_{e8c37195-128a-4aa0-b681-9b6788fcec2f}_minwidth=0.381 midlayer3_{e8c37195-128a-4aa0-b681-9b6788fcec2f}_maxwidth=0.381 midlayer3_{e8c37195-128a-4aa0-b681-9b6788fcec2f}_prefwidth=0.381 midlayer4_{e8c37195-128a-4aa0-b681-9b6788fcec2f}_minwidth=0.381 midlayer4_{e8c37195-128a-4aa0-b681-9b6788fcec2f}_maxwidth=0.381 midlayer4_{e8c37195-128a-4aa0-b681-9b6788fcec2f}_prefwidth=0.381 bottomlayer_{e8c37195-128a-4aa0-b681-9b6788fcec2f}_minwidth=0.381 bottomlayer_{e8c37195-128a-4aa0-b681-9b6788fcec2f}_maxwidth=0.381 bottomlayer_{e8c37195-128a-4aa0-b681-9b6788fcec2f}_prefwidth=0.381 substack13={92E0C252-34CC-4501-B85F-B111C59C3287} toplayer_{92e0c252-34cc-4501-b85f-b111c59c3287}_minwidth=0.381 toplayer_{92e0c252-34cc-4501-b85f-b111c59c3287}_maxwidth=0.381 toplayer_{92e0c252-34cc-4501-b85f-b111c59c3287}_prefwidth=0.381 midlayer1_{92e0c252-34cc-4501-b85f-b111c59c3287}_minwidth=0.381 midlayer1_{92e0c252-34cc-4501-b85f-b111c59c3287}_maxwidth=0.381 midlayer1_{92e0c252-34cc-4501-b85f-b111c59c3287}_prefwidth=0.381 midlayer2_{92e0c252-34cc-4501-b85f-b111c59c3287}_minwidth=0.381 midlayer2_{92e0c252-34cc-4501-b85f-b111c59c3287}_maxwidth=0.381 midlayer2_{92e0c252-34cc-4501-b85f-b111c59c3287}_prefwidth=0.381 midlayer3_{92e0c252-34cc-4501-b85f-b111c59c3287}_minwidth=0.381 midlayer3_{92e0c252-34cc-4501-b85f-b111c59c3287}_maxwidth=0.381 midlayer3_{92e0c252-34cc-4501-b85f-b111c59c3287}_prefwidth=0.381 midlayer4_{92e0c252-34cc-4501-b85f-b111c59c3287}_minwidth=0.381 midlayer4_{92e0c252-34cc-4501-b85f-b111c59c3287}_maxwidth=0.381 midlayer4_{92e0c252-34cc-4501-b85f-b111c59c3287}_prefwidth=0.381 bottomlayer_{92e0c252-34cc-4501-b85f-b111c59c3287}_minwidth=0.381 bottomlayer_{92e0c252-34cc-4501-b85f-b111c59c3287}_maxwidth=0.381 bottomlayer_{92e0c252-34cc-4501-b85f-b111c59c3287}_prefwidth=0.381 substack14={732F7058-E977-446F-8A06-ECA871B5D75E} toplayer_{732f7058-e977-446f-8a06-eca871b5d75e}_minwidth=0.381 toplayer_{732f7058-e977-446f-8a06-eca871b5d75e}_maxwidth=0.381 toplayer_{732f7058-e977-446f-8a06-eca871b5d75e}_prefwidth=0.381 midlayer1_{732f7058-e977-446f-8a06-eca871b5d75e}_minwidth=0.381 midlayer1_{732f7058-e977-446f-8a06-eca871b5d75e}_maxwidth=0.381 midlayer1_{732f7058-e977-446f-8a06-eca871b5d75e}_prefwidth=0.381 midlayer2_{732f7058-e977-446f-8a06-eca871b5d75e}_minwidth=0.381 midlayer2_{732f7058-e977-446f-8a06-eca871b5d75e}_maxwidth=0.381 midlayer2_{732f7058-e977-446f-8a06-eca871b5d75e}_prefwidth=0.381 midlayer3_{732f7058-e977-446f-8a06-eca871b5d75e}_minwidth=0.381 midlayer3_{732f7058-e977-446f-8a06-eca871b5d75e}_maxwidth=0.381 midlayer3_{732f7058-e977-446f-8a06-eca871b5d75e}_prefwidth=0.381 midlayer4_{732f7058-e977-446f-8a06-eca871b5d75e}_minwidth=0.381 midlayer4_{732f7058-e977-446f-8a06-eca871b5d75e}_maxwidth=0.381 midlayer4_{732f7058-e977-446f-8a06-eca871b5d75e}_prefwidth=0.381 bottomlayer_{732f7058-e977-446f-8a06-eca871b5d75e}_minwidth=0.381 bottomlayer_{732f7058-e977-446f-8a06-eca871b5d75e}_maxwidth=0.381 bottomlayer_{732f7058-e977-446f-8a06-eca871b5d75e}_prefwidth=0.381 maxuncoupledlength=25.4
FabricationTestPointUsage TestPointUsage [All] p1: valid=2 allowmultiple=FALSE
FabricationTestpoint Testpoint [All] p1: side=3 testpointundercomponent=TRUE minsize=1.016 maxsize=2.54 preferedsize=1.524 minholesize=0 maxholesize=1.016 preferedholesize=0.813 testpointgrid=0.025 allowsidetop=TRUE allowsidebottom=TRUE usegrid=TRUE gridtolerance=0
FanoutControl Fanout_LCC [IsLCC] p1: bgadir=Out bgaviamode=Centered fanoutstyle=Auto fanoutdirection=Alternating viagrid=0.025 // Fanout_LCC (Default Rule)
FanoutControl Fanout_BGA [IsBGA] p2: bgadir=Out bgaviamode=Centered fanoutstyle=Auto fanoutdirection=Alternating viagrid=0.025 // Fanout_BGA (Default Rule)
FanoutControl Fanout_Default [All] p4: bgadir=Out bgaviamode=Centered fanoutstyle=Auto fanoutdirection=Alternating viagrid=0.025 // Fanout_Default (Default Rule)
FanoutControl Fanout_Small [(CompPinCount < 5)] p5: bgadir=Out bgaviamode=Centered fanoutstyle=Auto fanoutdirection=OutThenIn viagrid=0.025 // Fanout_Small (Default Rule)
HoleSize [All] p1: absolutevalues=TRUE maxlimit=6.375 minlimit=0.152 maxpercent=80.000 minpercent=20.000
MinimumAnnularRing MinimumAnnularRing_ThermalPadVias [IsVia and InAnyComponent] p1: minimumring=0.114
MinimumAnnularRing [IsVia] p2: minimumring=0.114
MinimumSolderMaskSliver MinimumSolderMaskSliver_Logo [InComponentClass('Logo') vs InComponentClass('Logo')] p1: minsoldermaskwidth=0
MinimumSolderMaskSliver [All] p2: minsoldermaskwidth=0
PlaneConnect [All] p1: planeconnectstyle=Direct reliefexpansion=0.254 reliefentries=4 reliefconductorwidth=0.254 reliefairgap=0.254
PolygonConnect GaN [HasFootprint('RQS0052C-C01-MFG') And OnLayer('Bottom Layer') vs InNet('SW') or InNet('PGND') OR InNet('HVBUS')] p1: connectstyle=Direct reliefconductorwidth=0.254 reliefentries=4 polygonreliefangle="90 Angle" airgapwidth=0.254
PolygonConnect [All] p2: connectstyle=Direct reliefconductorwidth=0.254 reliefentries=4 polygonreliefangle="90 Angle" airgapwidth=0.254
RoomDefinition "GaN Card_Hardware" [InComponentClass('GaN Card_Hardware')] p1: confinementstyle=ConfineIn formatcopy=TRUE lockcomponents=FALSE outline -48.358,-72.387 2.442,-72.387 2.442,-46.987 -48.358,-46.987
RoomDefinition "GaN Card" [InComponentClass('GaN Card')] p2: confinementstyle=ConfineIn formatcopy=TRUE lockcomponents=FALSE outline -48.358,-72.387 2.442,-72.387 2.442,-46.987 -48.358,-46.987
RoutingVias ThermalPadVias [IsVia and InAnyComponent] p1: holewidth=0.2 width=0.5 viastyle="Through Hole" minholewidth=0.2 minwidth=0.5 maxholewidth=0.33 maxwidth=0.6
RoutingVias [All] p2: holewidth=0.254 width=0.508 viastyle="Through Hole" minholewidth=0.152 minwidth=0.254 maxholewidth=1.016 maxwidth=1.651
SMDToCorner [All] p1: distance=30000
SilkToBoardRegionClearance [Not ((IsComment or IsDesignator) And (Hide <> 'False')) and not InRegion(1000,500,4000,800)] p1:
SilkToSilkClearance [All] p1: silktosilkclearance=0
SilkToSolderMaskClearance SilkscreenOverComponentPads [IsPad] p1: minsilkscreentomaskgap=0 clearancetoexposedcopper=TRUE
SolderMaskExpansion [All] p1: expansion=0.05 istentingtop=FALSE
Width [All] p1: maxlimit=25.4 minlimit=0.152 preferedwidth=0.254 substack1={A02F224D-4808-492E-A71F-5F5656FBF0D4} substack2={B838D286-A00B-4EE2-88E1-F79279CC64B4} substack3={88BCB183-C685-456E-B90A-365A53404C2C} substack4={4C8C2325-90D5-40B8-8B6B-4F66D44EFE25} substack5={553D66F5-99EF-40B1-BA7C-73E3B04B176F} substack6={FF0C9878-5A48-402E-B013-8E2EEFCEDCCB} substack7={5BB5B65B-6C7F-4868-A6AE-66DD57ADDCBD} substack8={590F0BEA-1E04-4904-B9C9-D9D160075BC2} substack9={B2AC4F48-1A5F-44D7-A91B-3BAADFDAAED0} substack10={DD3D4156-A54D-4E1F-B7FF-E5EF72C45496} substack11={7CC4AE65-1EB7-43C1-8FCA-3677EE54F737} substack12={E8C37195-128A-4AA0-B681-9B6788FCEC2F} substack13={92E0C252-34CC-4501-B85F-B111C59C3287} substack14={732F7058-E977-446F-8A06-ECA871B5D75E} checkconnectedcopper=TRUE
15 further rules are at their usual default settings.

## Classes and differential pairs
net class Screw: NC1 NC2 NC3
component class "GaN Card_Hardware": J1 J2 TP1 TP2 TP3 TP4 TP5 TP6
net class INGND: 3V3 5V0 DGND EN EN_DRV "EN_ISO 12V" GaN_FAULT HS_FAULT HS_OC HS_PWM HS_PWM_IN HS_TEMP LS_FAULT LS_OC LS_PWM LS_PWM_IN LS_TEMP NCU7 NetC3_1 NetC4_1 NetC26_1 NetC27_1 NetC38_1 NetR11_1 NetR12_1 NetR13_1 NetR21_1 NetR22_1 NetR23_1 NetT1_4 NetT1_6
net class VSWNET: 5V_H ISO_12V_H NCT1 NCU61 NCU517 NCU527 NCU543 NCU547 NCU552 NCU616 NetC9_1 NetC9_2 NetC10_2 NetC13_2 NetC17_2 NetC18_1 NetD2_2 NetL1_2 NetR5_2 NetU2_3 NetU2_4 NetU2_5 SW
net class VHV: HVBUS NCU51 NCU516
net class PGND: 5V_L ISO_12V_L NCU617 NCU627 NCU643 NCU647 NCU652 NetC14_2 NetC16_2 NetC20_1 NetL2_2 NetR6_1 NetU3_3 NetU3_4 NetU3_5 PGND
component class "GaN Card": C1 C2 C3 C4 C5 C6 C7 C8 C9 C10 C11 C12 C13 C14 C15 C16 C17 C18 C19 C20 C21 C22 C23 C24 C25 C26 C27 C28 C30 C32 C33 C34 C35 C36 C37 C38 C39 "CAUTION HOT SURFACE" D2 D3 "DANGER HIGH VOLTAGE" L1 L2 L3 LBL1 Logo1 Logo3 Logo4 R1 R2 R3 R4 R5 R6 R7 R8 R9 R10 R11 R12 R13 R14 R15 R16 R21 R22 R23 R25 T1 TH1 TH2 TH3 U1 U2 U3 U4 U5 U6 U7 U8

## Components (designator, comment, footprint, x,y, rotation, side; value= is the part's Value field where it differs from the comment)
C1 "GCM155R71H104KE02D" 0402 2.9,28.214 r90 top value=0.1uF
C2 "CGA4J1X7R1E475K125AC" 0805 8.4,28.15 r90 top value=4.7uF
C3 "CGA2B2C0G1H101J050BA" 0402 44.845,24.565 r180 top value=100pF
C4 "CGA2B2C0G1H101J050BA" 0402 44.845,12.246 r180 top value=100pF
C5 "GRT155C71A105KE13D" 0402 42.142,30.772 r0 top value=1uF
C6 "GRT155C71A105KE13D" 0402 44.845,19.344 r0 top value=1uF
C7 "GRT155C71A105KE13D" 0402 34.711,24.565 r90 top value=1uF
C8 "GRT155C71A105KE13D" 0402 34.711,12.856 r270 top value=1uF
C9 "CGA4J1X7R1E475K125AC" 0805L 8.676,10.875 r0 top value=4.7uF
C10 "CGA4J1X7R1E475K125AC" 0805L 8.676,13.198 r180 top value=4.7uF
C11 "GCM31CC71E106KA03L" 1206_190 32.4,31.3 r0 top value=10uF
C12 "GCM31CC71E106KA03L" 1206_190 32.4,18.45 r0 top value=10uF
C13 "CGA2B2C0G1H101J050BA" 0402 32.755,16.513 r180 top value=100pF
C14 "CGA2B2C0G1H101J050BA" 0402 32.755,26.221 r180 top value=100pF
C15 "GCM155R71C224KE02D" 0402 32.755,11.003 r180 top value=0.22uF
C16 "CGA2B2C0G1H101J050BA" 0402 32.755,29.538 r180 top value=100pF
C17 "CGA2B2C0G1H101J050BA" 0402 32.755,13.237 r180 top value=100pF
C18 "GCM21BR71E225KA73L" 0805_HV 27.04,16.437 r270 top value=2.2uF
C19 "GCM155R71C224KE02D" 0402 32.755,23.842 r180 top value=0.22uF
C20 "GCM21BR71E225KA73L" 0805_HV 27.04,29.391 r270 top value=2.2uF
C21 "CGA4J1X7R1E475K125AC" 0805L 10.825,8.356 r270 top value=4.7uF
C22 "C1206C223KDRACTU" 1206_190 26.53,9.281 r90 top value=0.022uF
C23 "C1206C223KDRACTU" 1206_190 28.562,9.281 r90 top value=0.022uF
C24 "C1812W104KDRACTU" 1812_254 23.593,9.249 r90 top value=0.1uF
C25 "C1812W104KDRACTU" 1812_254 20.01,9.249 r90 top value=0.1uF
C26 "GCM155R71H104KE02D" 0402 48.489,8.899 r90 bottom value=0.1uF
C27 "GCM155R71H104KE02D" 0402 45.727,37.26 r270 top value=0.1uF
C28 "GCM155R71H104KE02D" 0402 45.845,6.715 r180 bottom value=0.1uF
C30 "GCM155R71H104KE02D" 0402 4.901,30.446 r180 top value=0.1uF
C32 "GCQ1555C1H430JB01D" 0402 44.845,30.772 r180 top value=43pF
C33 "GCQ1555C1H430JB01D" 0402 42.952,11.078 r180 top value=43pF
C34 "GCQ1555C1H430JB01D" 0402 45.658,11.078 r0 top value=43pF
C35 "GCQ1555C1H430JB01D" 0402 44.845,18.088 r180 top value=43pF
C36 "GCM155R71H104KE02D" 0402 46.659,8.563 r90 top value=0.1uF
C37 "GCM155R71H104KE02D" 0402 42.118,32.169 r0 top value=0.1uF
C38 "CGA2B3X7R1H103K050BB" 0402 45.757,34.284 r90 top value=0.01uF
C39 "GRT155C71A105KE13D" 0402 44.845,32.169 r180 top value=1uF
"CAUTION HOT SURFACE" "CAUTION HOT SURFACE" IEC_HotSurface_Small 19.274,22.009 r0 top
D2 "MBR0520LT1G" SOD-123 4.097,10.976 r180 top value=20V
D3 "MBR0520LT1G" SOD-123 4.758,13.389 r0 top value=20V
"DANGER HIGH VOLTAGE" "DANGER HIGH VOLTAGE" IEC_HighVoltage_Small 19.325,29.21 r0 top
J1 "FTSH-106-01-L-D-RA" FP-FTSH-106-01-L-D-RA_HDR12-MFG 45.314,0.45 r180 top
J2 "FTSH-102-01-L-D-RA" FP-FTSH-102-01-L-D-RA_HDR4-MFG 2.265,0.463 r180 top
L1 "SDEM20161T-4R7MS" FP-SDEM20161T-4R7MS_SMD2-MFG 29.445,15.794 r90 top
L2 "SDEM20161T-4R7MS" FP-SDEM20161T-4R7MS_SMD2-MFG 29.362,29.205 r90 top
L3 "ACT32P-102-2P-TL01" FP-ACT32P-102-2P-TL01_SMT4_3MM9_2MM5-MFG 7.376,8.156 r180 top
LBL1 "THT-14-423-10" Label_650x200 6.476,18.655 r90 bottom
Logo1 "CE Mark" CE_Mark_5mm 44.065,26.965 r180 bottom
Logo3 "FCC disclaimer" FCC_disclaimer 22.98,24.72 r180 bottom
Logo4 "WEEE logo" WEEE_Minimum 44.255,18.82 r180 bottom
R1 "CRCW040249R9FKED" 0402 44.845,25.784 r180 top value=49.9
R2 "CRCW040249R9FKED" 0402 44.845,13.465 r180 top value=49.9
R3 "CRCW0402100RFKED" 0402 48.489,6.454 r90 bottom value=100
R4 "CRCW0402100RFKED" 0402 47.005,37.26 r90 top value=100
R5 "CRCW040249R9FKED" 0402 32.755,15.396 r0 top value=49.9
R6 "CRCW040249R9FKED" 0402 32.755,28.375 r180 top value=49.9
R7 "CRCW0402100KFKED" 0402 32.755,27.32 r180 top value=100k
R8 "MCS0402MD1002BE100" 0402 45.845,5.505 r0 bottom value=10.0k
R9 "CRCW0402100KFKED" 0402 32.755,14.278 r180 top value=100k
R10 "ERJ-2GE0R00X" 0402 32.755,25.027 r0 top value=0
R11 "CRCW0402300RJNED" 0402 44.845,27.004 r0 top value=300
R12 "CRCW0402300RJNED" 0402 44.845,28.197 r0 top value=300
R13 "CRCW040220R0FKED" 0402 44.845,29.366 r0 top value=20.0
R14 "MCS0402MD1002BE100" 0402 48.335,37.27 r270 top value=10.0k
R15 "ERJ-2GE0R00X" 0402 32.755,12.195 r180 top value=0
R16 "CRCW04020000Z0EDHP" 0402 7.526,30.446 r180 top value=0
R21 "CRCW0402300RJNED" 0402 44.845,14.634 r0 top value=300
R22 "CRCW0402300RJNED" 0402 44.845,15.828 r0 top value=300
R23 "CRCW040220R0FKED" 0402 44.845,16.971 r0 top value=20.0
R25 "CRCW12060000Z0EA" 1206 14.445,34.48 r180 top value=0
T1 "760390014" Wurth_760390013 5.5,19.85 r90 top value=475uH
TH1 "" TP_H045P075#1 10.517,19.243 r90 top
TH2 "" TP_H045P075#2 37.2,36.314 r90 top
TH3 "" TP_H045P075#3 36.127,8.436 r90 top
TP1 "3621-0-32-15-00-00-08-0" Mill-Max_3621-0-32-xx-00-00-08-0 25.03,-0.797 r0 top
TP2 "3621-0-32-15-00-00-08-0" Mill-Max_3621-0-32-xx-00-00-08-0 5.45,-0.8 r0 top
TP3 "3621-0-32-15-00-00-08-0" Mill-Max_3621-0-32-xx-00-00-08-0 14.93,-0.8 r0 top
TP4 "3621-0-32-15-00-00-08-0" Mill-Max_3621-0-32-xx-00-00-08-0 28.835,-0.797 r0 top
TP5 "3621-0-32-15-00-00-08-0" Mill-Max_3621-0-32-xx-00-00-08-0 9.25,-0.8 r0 top
TP6 "3621-0-32-15-00-00-08-0" Mill-Max_3621-0-32-xx-00-00-08-0 18.73,-0.8 r0 top
U1 "SN6505DQDBVRQ1" DBV0006A_N 5.496,27.603 r90 top
U2 "ISO7741FQDBQRQ1" DBQ0016A-MFG 39.181,15.345 r0 top
U3 "ISO7741FQDBQRQ1" DBQ0016A-MFG 39.156,27.207 r0 top
U4 "LMG3522R030-Q1" RQS0052C-C01-MFG 24.246,12.754 r90 bottom
U5 "LMG3522R030-Q1" RQS0052C-C01-MFG 24.246,26.508 r90 bottom
U6 "SN74AHC1G08QDBVRQ1" DBV0005A_N 44.083,8.563 r270 top
U7 "TPS71733QDRVRQ1" DRV0006A 43.357,34.2 r180 top
U8 "SN74LVC2G66QDCURQ1" DCU0008A-MFG 45.515,8.395 r0 bottom

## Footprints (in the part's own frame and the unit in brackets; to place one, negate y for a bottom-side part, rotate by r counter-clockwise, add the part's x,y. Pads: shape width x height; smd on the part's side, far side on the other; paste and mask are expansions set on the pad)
0402 [mm] "0402 from SM-752 data"
  rect 0.8x0.6 smd: 1(-0.6,0) 2(0.6,0)
  silkscreen extent -1.22,-0.52 1.22,0.52, body extent -0.55,-0.3 0.55,0.3, height 0.6
0805 [mm] "0805 from SM-752 data"
  rect 1.3x1.5 smd: 1(-0.85,0) 2(0.85,0)
  silkscreen extent -1.72,-0.97 1.72,0.97, body extent -1.1,-0.72 1.1,0.72, height 1.45
0805_HV [mil] "0805 with 30mil clearance between pads"
  rect 50x63 smd: 1(-40,0) 2(40,0)
  silkscreen extent -74,-40 74,40, body extent -43,-29 43,29, height 57
0805L [mm] "0805 from SM-752 data"
  rect 1.1x1.4 smd: 1(-0.75,0) 2(0.75,0)
  body extent -1.1,-0.72 1.1,0.72, height 1.45
1206 [mm] "1206 from SM-752 data"
  rect 1.3x1.85 smd: 1(-1.45,0) 2(1.45,0)
  silkscreen extent -2.4,-1.21 2.4,1.21, body extent -1.7,-0.9 1.7,0.9, height 1.35
1206_190 [mm] "1206_190"
  rect 1.1x1.6 smd: 1(-1.7,0) 2(1.7,0)
  silkscreen extent -0.9,-1 0.9,1, body extent -1.75,-0.95 1.75,0.95, height 1.9
1812_254 [mm] "SMD, 2-Leads, Body 4.8x3.4mm"
  rect 1.6x3.4 smd: 1(-2,0) 2(2,0)
  silkscreen extent -0.8,-1.7 0.8,1.7, body extent -2.4,-1.7 2.4,1.7, height 2.54
CE_Mark_5mm [mm] "Minimum text height for CE Mark"
  silkscreen extent -3.5,-2.5 3.5,2.5
DBQ0016A-MFG [mm]
  rrect24% 1.6x0.41 smd paste+0 mask+0: 1(-2.7,2.222) 2(-2.7,1.587) 3(-2.7,0.953) 4(-2.7,0.318) 5(-2.7,-0.318) 6(-2.7,-0.953) 7(-2.7,-1.587) 8(-2.7,-2.222) 9(2.7,-2.222) 10(2.7,-1.587) 11(2.7,-0.953) 12(2.7,-0.318) 13(2.7,0.318) 14(2.7,0.953) 15(2.7,1.587) 16(2.7,2.222)
  silkscreen extent -4.17,-2.5 1.5,2.5, body extent -3.6,-2.75 3.6,2.75, height 0.25
DBV0005A_N [mm] "SOT23, 5-Leads, Body 2.9x1.6mm, Pitch 0.95mm, Lead Span 2.8mm, IPC Medium Density"
  rrect17% 1x0.6 smd: 1(-1.375,0.95) 2(-1.375,0) 3(-1.375,-0.95) 4(1.375,-0.95) 5(1.375,0.95)
  silkscreen extent -1.63,-1.55 0.38,1.55, body extent -1.42,-1.46 1.42,1.46, height 1.09
DBV0006A_N [mm] "SOT23, 6-Leads, Body 2.9x1.6mm, Pitch 0.95mm, Lead Span 2.8mm, IPC Medium Density"
  rrect17% 1x0.6 smd: 1(-1.375,0.95) 2(-1.375,0) 3(-1.375,-0.95) 4(1.375,-0.95) 5(1.375,0) 6(1.375,0.95)
  silkscreen extent -1.68,-1.55 0.5,1.55, body extent -1.42,-1.46 1.42,1.46, height 1.12
DCU0008A-MFG [mm]
  rrect33% 0.85x0.3 smd paste+0 mask+0: 1(-1.55,0.75) 2(-1.55,0.25) 3(-1.55,-0.25) 4(-1.55,-0.75) 5(1.55,-0.75) 6(1.55,-0.25) 7(1.55,0.25) 8(1.55,0.75)
  silkscreen extent -2.65,-1.05 0.75,1.05, body extent -1.55,-1 1.55,1, height 0.9
DRV0006A [mm] "SON, 6-Leads, Body 2x2mm, Pitch 0.65mm, Thermal Pad 1.6x1mm, TI Recommended"
  rrect33% 0.45x0.3 smd: 1(-0.975,0.65) 2(-0.975,0) 3(-0.975,-0.65) 4(0.975,-0.65) 5(0.975,0) 6(0.975,0.65)
  rrect14% 1x0.7 on Top Paste: 7(0,0.45) 7(0,-0.45)
  rrect10% 1x1.6 smd paste-0.5: 7(0,0)
  silkscreen extent -1.05,-1.2 1.05,1.2, body extent -1.05,-1.05 1.05,1.05, height 0.81
FCC_disclaimer [mm]
FP-ACT32P-102-2P-TL01_SMT4_3MM9_2MM5-MFG [mm]
  rrect17% 1.05x0.6 smd paste+0 mask+0: 1(-1.525,0.5) 2(-1.525,-0.5) 3(1.525,-0.5) 4(1.525,0.5)
  silkscreen extent -1.93,-1.35 1.7,2.07, body extent -2.15,-1.45 2.15,1.45, height 0.25
FP-FTSH-102-01-L-D-RA_HDR4-MFG [mm]
  rrect9% 0.95x0.95 hole 0.7 paste-1000 mask+0: 1(0.635,-2.525)
  round 0.95 hole 0.7 paste-1000 mask+0: 2(0.635,-3.795) 3(-0.635,-2.525) 4(-0.635,-3.795)
  silkscreen extent -1.3,-2.65 1.87,1.32, body extent -1.4,-4.45 1.4,4.6, height 0.25
FP-FTSH-106-01-L-D-RA_HDR12-MFG [mm]
  rrect9% 1x1 hole 0.71 paste-1000 mask+0: 1(3.175,-2.525)
  round 1 hole 0.71 paste-1000 mask+0: 2(3.175,-3.795) 3(1.905,-2.525) 4(1.905,-3.795) 5(0.635,-2.525) 6(0.635,-3.795) 7(-0.635,-2.525) 8(-0.635,-3.795) 9(-1.905,-2.525) 10(-1.905,-3.795) 11(-3.175,-2.525) 12(-3.175,-3.795)
  silkscreen extent -3.84,-2.65 4.56,1.32, body extent -3.94,-4.45 3.94,4.6, height 0.25
FP-SDEM20161T-4R7MS_SMD2-MFG [mm]
  rrect15% 0.65x1.6 smd paste+0 mask+0: 1(-0.675,0) 2(0.675,0)
  silkscreen extent -1.05,-1.22 1.05,1.2, body extent -1.15,-0.95 1.15,0.95, height 0.25
IEC_HighVoltage_Small [mm]
  silkscreen extent -2.72,-2.24 2.72,2.47
IEC_HotSurface_Small [mm]
  silkscreen extent -2.72,-2.36 2.72,2.35
Label_650x200 [mil] "Thermal Transfer Label"
  round 1 on Mech14: 0(0,0)
  silkscreen extent -325,-100 325,100, body extent -325,-100 325,100, height 1
Mill-Max_3621-0-32-xx-00-00-08-0 [mm] "PCB Pin, 0.04\" DIA, R/A, Edge-Mount"
  rrect50% 3.18x3.18 hole 1.65: 1(0,2.388)
  body extent -1.59,-5.06 1.59,3.98, height 1.57
RQS0052C-C01-MFG [mm]
  rrect9% 1.15x1.1 smd paste+0 mask+0: 1(-5.725,5.2) 16(-5.725,-5.2) 27(5.725,-5.2) 42(5.725,5.2)
  rrect22% 1.15x0.45 smd paste+0 mask+0: 2(-5.725,4.225) 3(-5.725,3.575) 4(-5.725,2.925) 5(-5.725,2.275) 6(-5.725,1.625) 7(-5.725,0.975) 8(-5.725,0.325) 9(-5.725,-0.325) 10(-5.725,-0.975) 11(-5.725,-1.625) 12(-5.725,-2.275) 13(-5.725,-2.925) 14(-5.725,-3.575) 15(-5.725,-4.225) 28(5.725,-4.225) 29(5.725,-3.575) 30(5.725,-2.925) 31(5.725,-2.275) 32(5.725,-1.625) 33(5.725,-0.975) 34(5.725,-0.325) 35(5.725,0.325) 36(5.725,0.975) 37(5.725,1.625) 38(5.725,2.275) 39(5.725,2.925) 40(5.725,3.575) 41(5.725,4.225)
  rrect15% 0.665x1.15 smd paste+0 mask+0: 17(-2.043,-5.725) 52(-2.043,5.725)
  rrect22% 0.45x1.15 smd paste+0 mask+0: 18(-1.285,-5.725) 19(-0.635,-5.725) 20(0.015,-5.725) 21(0.665,-5.725) 22(1.315,-5.725) 23(1.965,-5.725) 24(2.615,-5.725) 25(3.265,-5.725) 26(3.915,-5.725) 43(3.915,5.725) 44(3.265,5.725) 45(2.615,5.725) 46(1.965,5.725) 47(1.315,5.725) 48(0.665,5.725) 49(0.015,5.725) 50(-0.635,5.725) 51(-1.285,5.725)
  silkscreen extent -7.02,-6.05 4.77,6.05, body extent -6,-6 6,6, height 1
SOD-123 [mm] "On Semi recommended land pattern"
  rect 0.915x1.22 smd: 1(-1.637,0) 2(1.637,0)
  silkscreen extent -2.74,-1.17 2.03,1.17, body extent -1.93,-0.9 1.93,0.9, height 1.35
TP_H045P075#1 [mm] "TP_H0.45P0.75"
  round 5.5 hole 3.2: 1(16.757,4.017)
TP_H045P075#2 [mm] "TP_H0.45P0.75"
  round 5.5 hole 3.2: 1(-0.314,0.7)
TP_H045P075#3 [mm] "TP_H0.45P0.75"
  round 5.5 hole 3.2: 1(-3.436,-0.373)
WEEE_Minimum [mm] "WEEElie bin"
  silkscreen extent -2.42,-4.38 2.52,2.65
Wurth_760390013 [mil] "Wurth"
  rect 44x38 smd: 1(-180,100) 2(-180,0) 3(-180,-100) 4(180,-100) 5(180,0) 6(180,100)
  silkscreen extent -190,-132 85,145, body extent -198,-135 198,130, height 166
